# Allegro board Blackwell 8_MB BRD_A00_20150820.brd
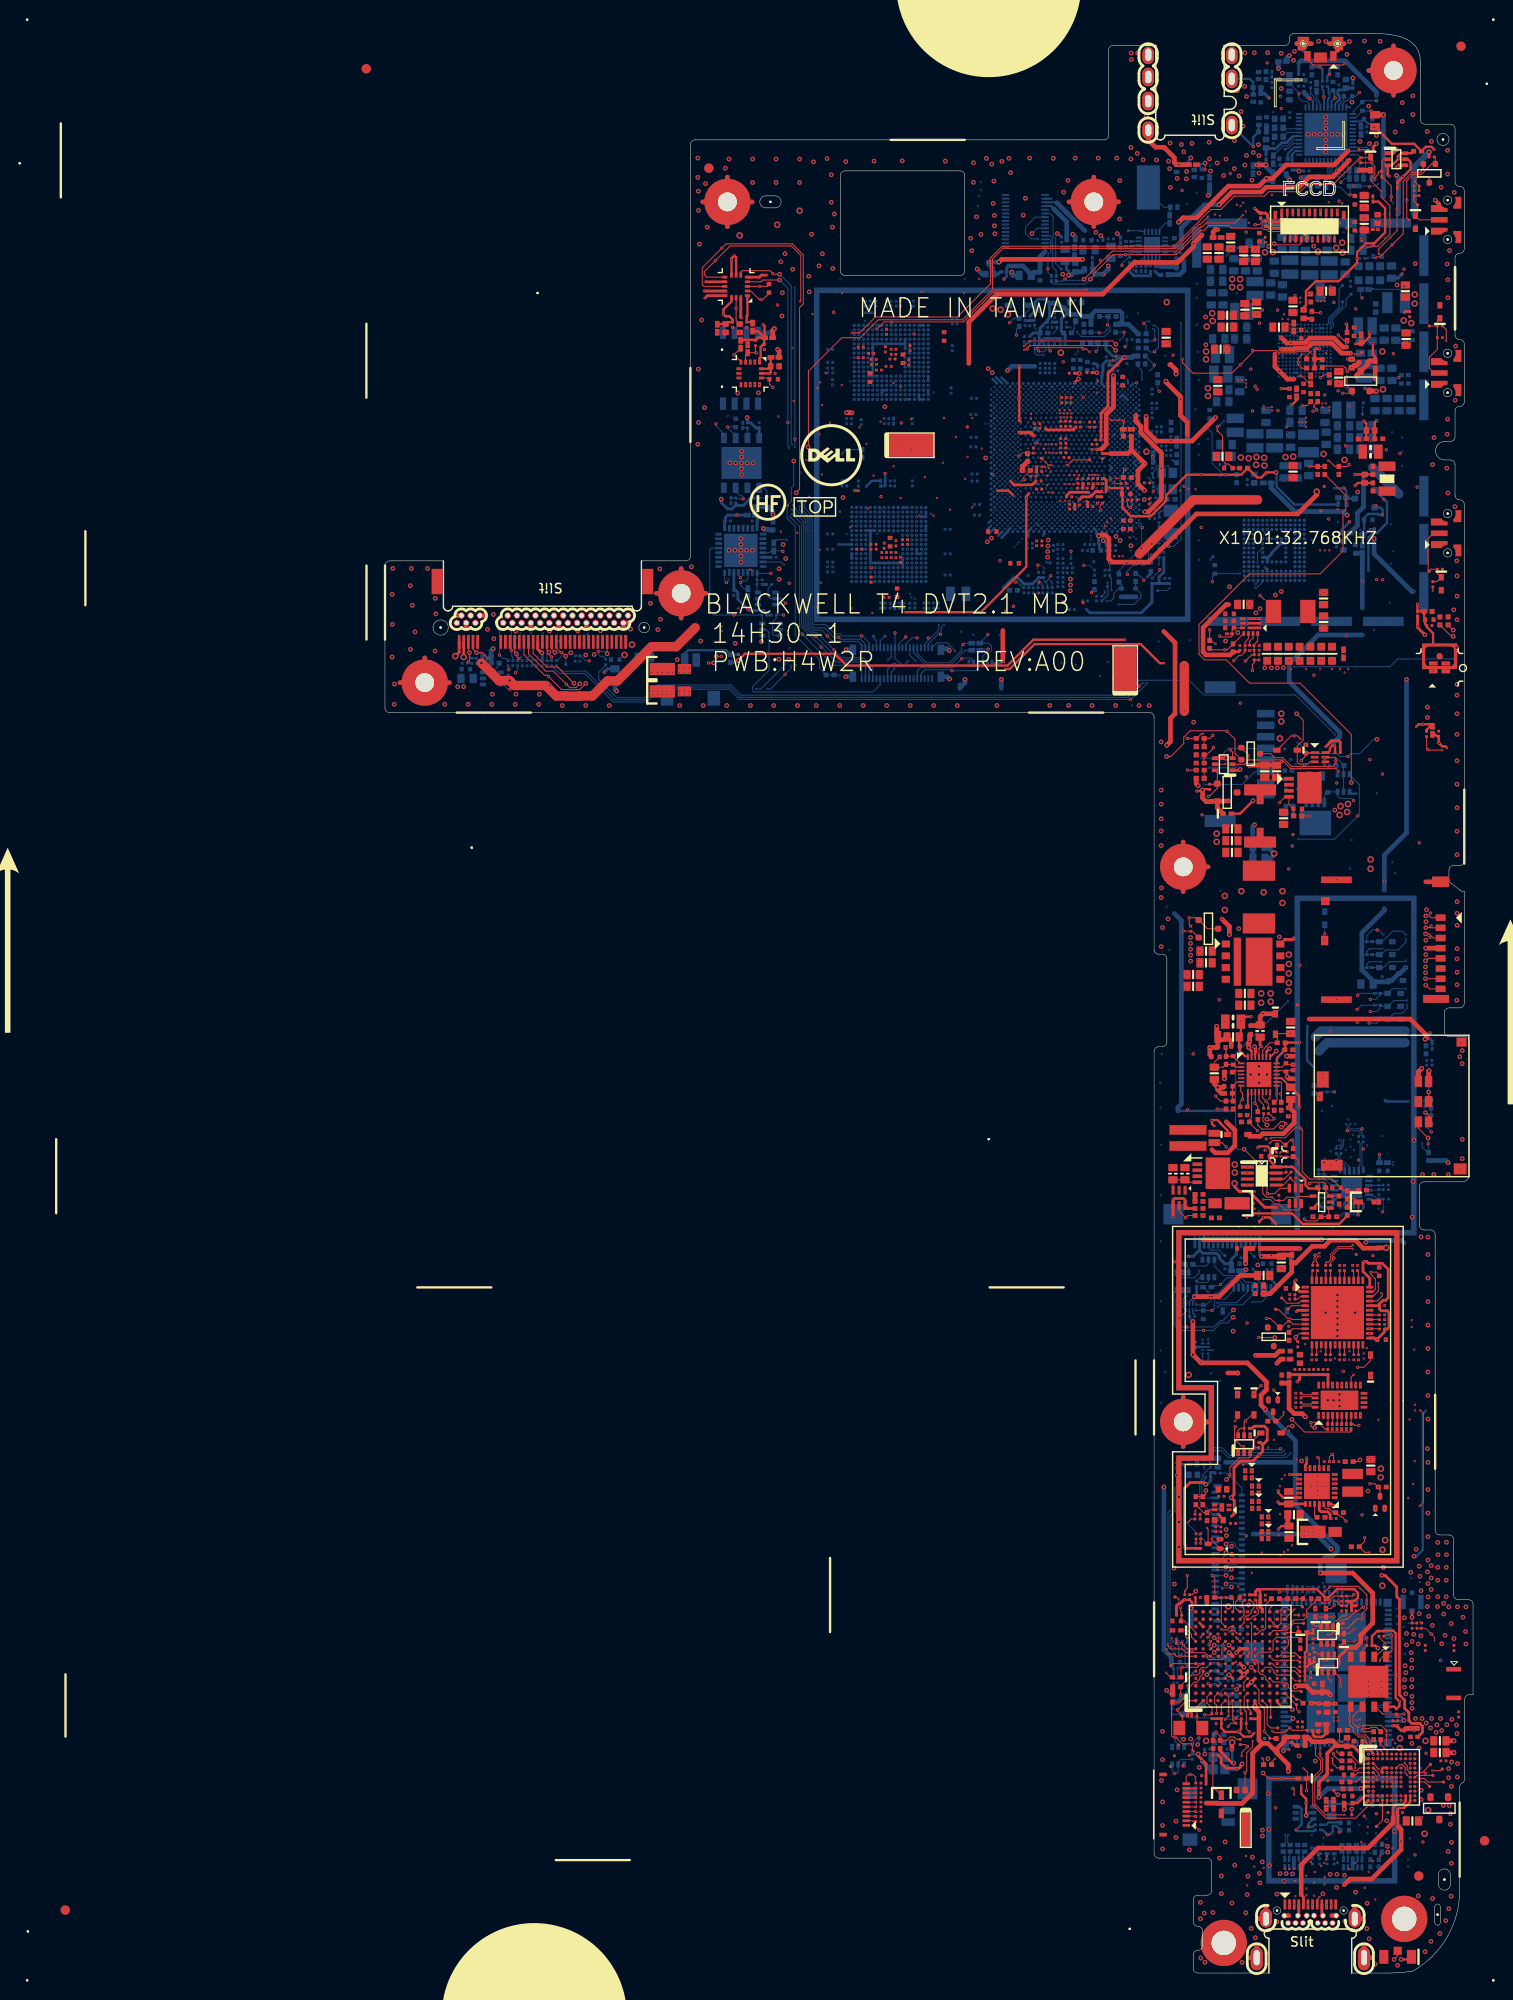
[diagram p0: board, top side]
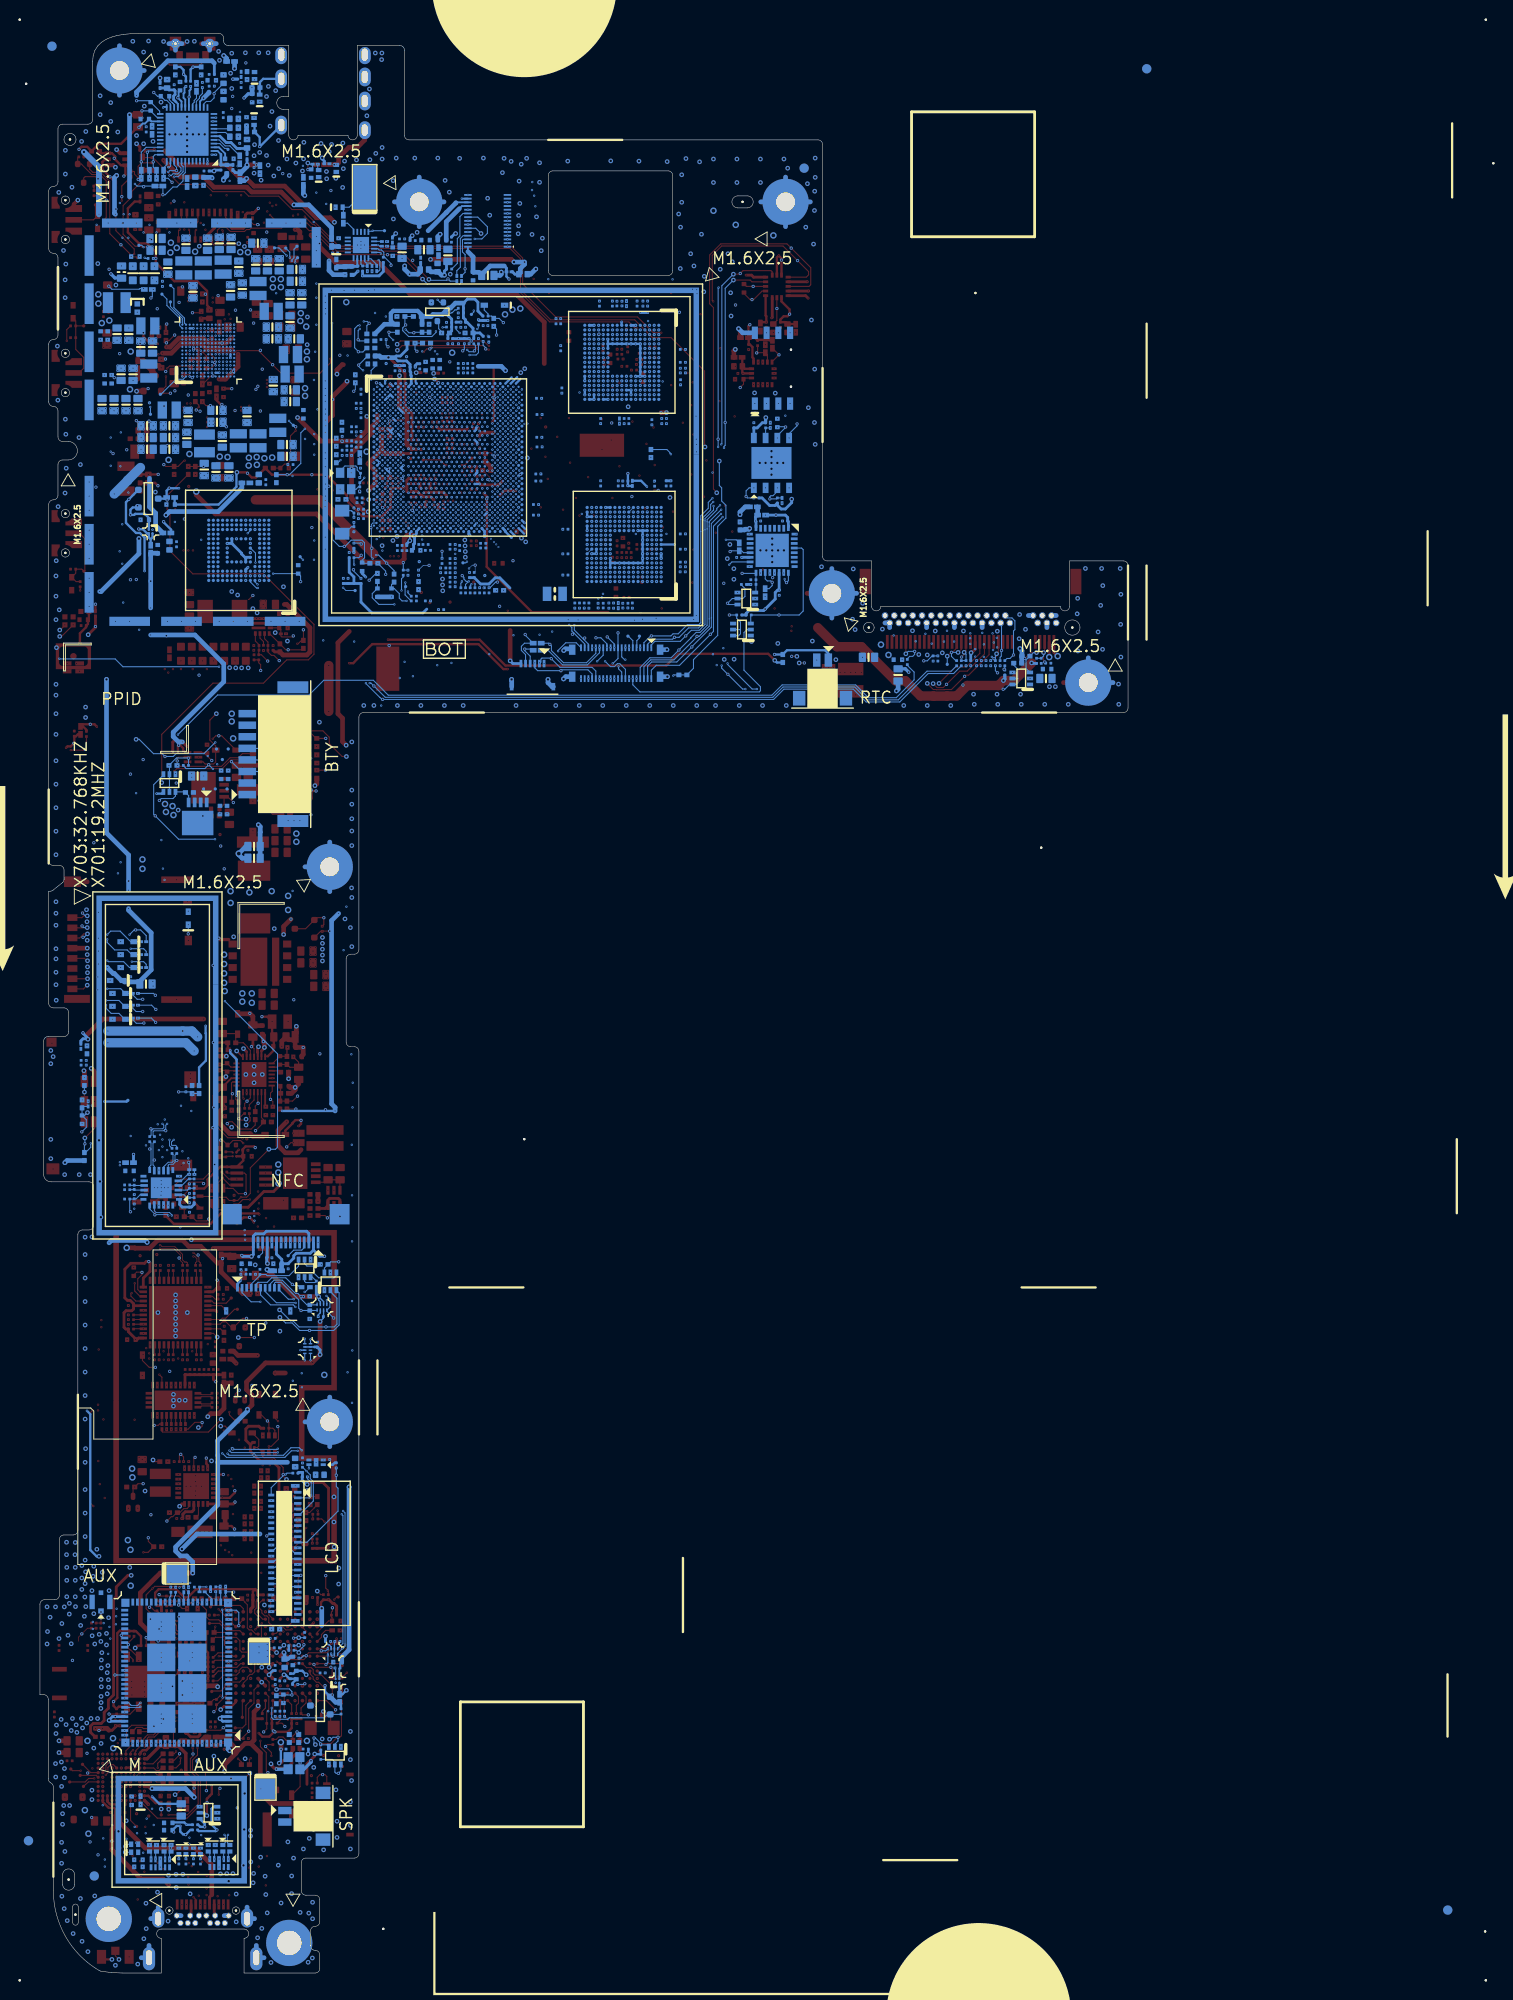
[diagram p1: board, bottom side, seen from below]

Outline 117.62 x 209.6 mm; copper layers: TOP, L2, L3SGND, L4SGND, L5, L6SGND, L7, BOTTOM. Coordinates in mm from the lower left corner of the outline.

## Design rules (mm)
constraint set DEFAULT: min track width 0.127, pair gap 0.102
net group 45R_EC_XTAL-MW: nets EC_XTAL1 EC_XTAL2
net group 45R_I2S-MW: nets CLK_I2S_MCLK CLK_I2S_MCLK_1
net group 45R_UART_BT-MW: nets UART_3_RXD_R UART_3_TXD_R
net group 45R_XTAL19D2M-MW: nets XTAL19_2_IN XTAL19_2_OUT
net group 45R_XTAL35D768K-MW: nets RTC_XTAL_IN RTC_XTAL_OUT
net group BIOS_HOLD#: nets BIOS_HOLD# FST_SPI_SOCK_D3
net group BIOS_WP#: nets BIOS_WP# FST_SPI_SOCK_D2
net group DDI0_TX0_DN: nets DDI0_TX0_DN DDI0_TX0_DN_ST
net group DDI0_TX0_DP: nets DDI0_TX0_DP DDI0_TX0_DP_ST
net group DDI0_TX1_DN: nets DDI0_TX1_DN DDI0_TX1_DN_ST
net group DDI0_TX1_DP: nets DDI0_TX1_DP DDI0_TX1_DP_ST
net group DDI0_TX2_DN: nets DDI0_TX2_DN DDI0_TX2_DN_ST
net group DDI0_TX2_DP: nets DDI0_TX2_DP DDI0_TX2_DP_ST
net group DDI0_TX3_DN: nets DDI0_TX3_DN DDI0_TX3_DN_ST
net group DDI0_TX3_DP: nets DDI0_TX3_DP DDI0_TX3_DP_ST
net group HP_MIC: nets HP_OUT_L HP_OUT_R
net group LPC_CLKOUT_0: nets LPC_CLKOUT_0 TPM_SCLK
net group MUX_ML0N: nets MUX_ML0N MUX_ML0N_ST
net group MUX_ML0P: nets MUX_ML0P MUX_ML0P_ST
net group MUX_ML1N: nets MUX_ML1N MUX_ML1N_ST
net group MUX_ML1P: nets MUX_ML1P MUX_ML1P_ST
net group MUX_ML2N: nets MUX_ML2N MUX_ML2N_ST
net group MUX_ML2P: nets MUX_ML2P MUX_ML2P_ST
net group MUX_ML3N: nets MUX_ML3N MUX_ML3N_ST
net group MUX_ML3P: nets MUX_ML3P MUX_ML3P_ST
net group SENSE: nets PMIC_VBATSENSE VSYS_SENSE_PMIC
net group USB3_0_RX+: nets USB3_0_RX+ USB3_0_RX+_L
net group USB3_0_RX-: nets USB3_0_RX- USB3_0_RX-_L
net group USB3_0_TX+: nets USB3_0_TX+ USB3_0_TX+_L
net group USB3_0_TX-: nets USB3_0_TX- USB3_0_TX-_L
net group USB3_A_INN: nets USB3_A_INN USB3_TXN0
net group USB3_A_INP: nets USB3_A_INP USB3_TXP0
net group USB3_B_OUTN: nets USB3_B_OUTN USB3_RXN0
net group USB3_B_OUTP: nets USB3_B_OUTP USB3_RXP0
net group 5V: nets +VUSB_5V_19V_R DCIN_OFF LCDBL_LED_A_R
net group 45R_CLK-MW: nets PLT_CLK1_CAM1 PLT_CLK1_CAM1_1 PLT_CLK1_CAM2 PLT_CLK1_CAM2_1
net group 45R_DDR_ZQ-MW: nets M0_ZQ0_A M0_ZQ0_B M0_ZQ1_A M0_ZQ1_B M1_ZQ0_A M1_ZQ0_B M1_ZQ1_A M1_ZQ1_B
net group 45R_DP_REDRIVER: nets DP_REDRIVER_ADDR_EQ DP_REDRIVER_CAD_SNK DP_REDRIVER_CAD_SRC DP_REDRIVER_EN_C DP_REDRIVER_RST DP_REDRIVER_SCL_CTL DP_REDRIVER_SCL_DDC DP_REDRIVER_SDA_CTL DP_REDRIVER_SDA_DDC DPR_HPD_IN DPR_HPD_OUT
net group 45R_EMMC-MW: nets EMMC_RESET#
net group 45R_EMMC_RCOMP-MW: nets EMMC_RCOMP
net group 45R_I2C-MW: nets CODEC_DMIC_1_DATA CODEC_DMIC_SCL DEBUG_I2C_1_SCL DEBUG_I2C_1_SDA DMIC_1_DATA DMIC_SCL GNSS0 GNSS1 GNSS_I2C_IRQ GYRO_CS I2C0_SCL I2C0_SDA I2C2_SCL I2C2_SDA I2C3_SCL I2C3_SDA I2C4_SCL I2C4_SDA I2C_0_SCL_EC I2C_0_SDA_EC I2C_1_SCL_CAM_R I2C_1_SCL_EC I2C_1_SDA_CAM_R I2C_1_SDA_EC I2C_4_SCL_EC I2C_4_SDA_EC I2C_5_SCL_3P3 I2C_5_SCL_EC I2C_5_SDA_3P3 I2C_5_SDA_EC I2C_7_SCL_EC I2C_7_SDA_EC I2CM_CLK I2CM_DATA ISH_I2C0_SCL ISH_I2C0_SDA ISH_I2C1_SCL ISH_I2C1_SCL_L ISH_I2C1_SDA ISH_I2C1_SDA_L PPMIC_DEBUG_I2C_CLK PPMIC_DEBUG_I2C_DATA PWR_CHG_CLK PWR_CHG_DATA RF_LTE_SIM1_CLK RF_LTE_SIM1_DATA SIM1_CLK_C SMB3_CLK_BATT SMB3_CLK_BATT_R SMB3_DAT_BATT SMB3_DAT_BATT_R TPS65982_I2C_ADDR TPS65982_I2C_IRQ1# TPS65982_I2C_SCL1 TPS65982_I2C_SCL2 TPS65982_I2C_SDA1 TPS65982_I2C_SDA2 TPS65982_SWD_CLK TPS65982_SWD_DATA
net group 45R_LPC-MW: nets LPC_AD0 LPC_AD1 LPC_AD2 LPC_AD3 LPC_CLKRUN# LPC_CLKRUN#_L LPC_FRAME# SOC_VBUSSNS
net group 45R_OTHER-MW: nets 2_4_LANE 2_4_LANE_DET 5V_COMP 5V_EN 5V_FB 5V_LBI 5V_LBO 5V_SVOUT AC_PRESENT AUDIO_CODEC_IRQ AUDIO_CODEC_IRQ_L AUDIO_CODEC_IRQ_R BPTHERM0 BRTC_EXTPAD BT_DEV_EN CAM_1_PWRDWN CAM_2_LSM CAM_2_PWRDWN COCO_ID CORE_PWROK DBG_RESETBTN# DCIN_DROP_DET# DDR3_DRAM_PWROK DDR3_VCCA_PWROK DEBUB_CS EC_BIST# GPIO133 GPIO223 GPIO224 GPIO_SUS3_C GYRO_INT1 HALL_INT# JACK_DET# LCD_BIST LCM_VDD_EN MIPI_BKLT_EN MIPI_PANEL_EN MODEM_SLPCLK NCF_SIMVCC NFC_SWP PANEL_EN PANEL_EN_L PANEL_EN_R PMIC_5V_EN PMIC_BATID PMIC_INT PMIC_LCM_BKLT_EN PMIC_LCM_BKLT_EN_R PMIC_PANEL_PWM0 PMIC_PANEL_PWM0_R PMIC_SYSTHERM0 PMIC_SYSTHERM1 PMIC_SYSTHERM2 PMIC_VBUS_IN PMIC_VDCIN PMU_BATTLOW# PROCHOT# RSMRST# SDIO_PWR_EN# SDMMC3_1P8_EN SLP_S0IX# SLP_S3# SLP_S4# SOC_PWRBTN# SOC_RTEST# SRT_CRST# SUS_PWRDOWNACK TOUCH_INT# TOUCH_RESET# TPM_GPIO0 TPM_GPIO0# USB_OTG_SOC_ID VBATL VOLUME_DOWN VOLUME_DOWN_SOC VOLUME_UP VOLUME_UP_SOC WL_DEV_EN WWAN_DETECT# WWAN_DETECT#_L
net group 45R_OTHERS-MW: nets 3V3_EC_EN 3V3_EC_VIN_ON# ACPI_INT# BATDRV# BATPRES# BL_FSET BL_ISET BOARD_ID CAMERA_1_RESET#_R CMP_7V+ CMP_7V- CODEC_CPN1 CODEC_CPN2 CODEC_CPP1 CODEC_CPP2 CODEC_CPVREF CODEC_DACREF CODEC_IN2P CODEC_VREF2 CPU_USB_OC# DBG_JTAG_CLK DBG_JTAG_RST# DBG_JTAG_TDI DBG_JTAG_TDO DBG_JTAG_TMS DBG_MSCLK DBG_MSDAT DBG_PIN1 DBG_UART_TX DCIN_OFF# DCIN_ON DDI0_HDP# DDI0_PLLOBS_N DDI0_PLLOBS_P DDI1_RCOMP_N DDI1_RCOMP_P DE303_INT1 DE303_INT2 DPR# EC5048_TX EC_AC_IN EC_AC_IN_R EC_BATT_PRES# EC_BATT_PRES#_R EC_FG_ALERT EC_GPIO002 EC_GPIO034 EC_GPIO036 EC_GPIO043 EC_GPIO047 EC_GPIO132 EC_GPIO201 EC_GPIO204 EC_GPIO212 EC_LAD0 EC_LAD1 EC_LAD2 EC_LAD3 EC_LCD_RST EC_LFRAME# EC_PROCHOT EC_PWRBTN# EC_RESETI# EC_SER_IRQ EC_SLP_S3# EC_SLP_S4# EC_SMI# EC_SMI#_R EC_SMI_REV# EC_SYS_PWR_EN EC_VCC_PWRGD EC_VCI_IN1# EC_VCI_IN2# EC_VCI_IN3# EC_VCI_IN4# EC_VCI_IN5# EC_VR_CAP EC_VREF_ADC ECOMPASS_C1 ECOMPASS_SETC ECOMPASS_SETP EN_19V_IN EN_19V_IN# EN_19V_IN_L EN_19V_IN_R EN_19V_IN_R# EN_DCIN_OP_VCC EN_V3P3_EC FG_ALERT_EC FSIN_REAR G601A31U_MRDLY GNSS_DISABLE# GNSS_DISABLE#_R GPIO151 GPIO152 GPIO166 GPIO222 GPIO_SUS2_C GPIO_SUS7 GYRO_CAP GYRO_INT2 GYRO_SA0 HOME_BTN_EC# HOME_BTN_SOC# HOME_KEY HOME_KEY_R HW_RST1 JACK_DET#_R LCD_BIST# LCM_HSYNC LCM_ID1 LCM_ID2 LCM_ID3 LCM_RST# LCM_XRES LCM_XRES1 LCM_XRES_R LRESET# MIC_CAP MODEM_PWR_ON MODEM_PWR_ON_R NFC_DWL_REQ NFC_EN_SEC NFC_HOST_INT_SEC OTG_ID P_RCOMP_N P_RCOMP_P PCIE_CLKREQ0# PEWAKE# PLTRST# PLTRST_EC PLTRST_N_3P3 PLTRST_N_3P3_R PMIC_PWRBTN# PMIC_PWRBTN_R# POWER_BUTTON_N PROJECT_ID1 PROJECT_ID2 PROX_CX PROX_CX_R PROX_DET# PWR_CHG_ACDET PWR_CHG_ACOK PWR_CHG_BATDRV# PWR_CHG_BTST PWR_CHG_BTST_A PWR_CHG_CELL PWR_CHG_CMPIN PWR_CHG_CMPIN_L PWR_CHG_CMSRC PWR_CHG_IADP PWR_CHG_PMON PWR_CHG_PROCHOT# PWR_CHG_REGN PWR_CHG_REGN_R PWR_SW_IN# R_OSC RF_LTE_SIM1_DET RF_LTE_SIM1_RST RF_W_DISABLE RF_W_DISABLE# RF_WWAN_DISABLE#_1P8 RTC_CLK SAR_A0 SAR_A1 SAR_INT SAR_INT_R SAR_RST SD3_CD# SIM_DETECT SLP_S0IX#_EC SLP_S0IX#_EC_R SLP_S3#_R SLP_S4#_R SOC_PROJECT_ID1 SOC_PROJECT_ID2 SPI_MODE SX_OFF SYS_PWR_ON SYS_PWR_ON# T0 T1 T2 T3 T4 T5 T6 T7 T8 T9 TOUCH_INT#_3P3 TOUCH_RESET#_3P3 TOUCH_RESET#_R TP_1P05_OBS TP_FUSE_PWRMON TP_ID1 TP_ID2 TP_VCCCORE2_OBS TP_VCCDDR_1P24_1P35_OBS TP_VCCSRAMGEN_1P15_OBS TP_VCCSRAMSOC_1P15_OBS TPS65982_DEBUG3 TPS65982_DEBUG3_R TPS65982_DEBUG4 TPS65982_DEBUG4_R TPS65982_GPIO0 TPS65982_GPIO0_R TPS65982_GPIO1 TPS65982_GPIO2 TPS65982_GPIO3 TPS65982_GPIO4_HPD TPS65982_GPIO6 TPS65982_GPIO7 TPS65982_GPIO8 TPS65982_I2C_IRQ2# TPS65982_I2C_IRQ2#_R TPS65982_LDO_BMC TPS65982_LSX_P2P TPS65982_LSX_P2R TPS65982_MRESET TPS65982_RESET# TPS65982_SS TPS65982_UART_RX TPS65982_UART_TX TPS65982_VOUT_3V3 TXE_WP TXE_WP# TYPE_C_IRQ# UART0_DBG_RXD UART0_DBG_TXD V3P3_SD_EN VCC0_SENSE VCC1_SENSE VCC_VSSSENSE VCCDSIPLL_1P24_1P35 VOLUME_DOWN_EC_IN VOLUME_DOWN_EC_OUT VOLUME_UP_EC_IN VOLUME_UP_EC_OUT VSET_EC WIFI_HOST_WAKE# WIFI_PERST# WWAN_WAKE# WWAN_WAKE_HOST#
net group 45R_REF_20MIL-MW: nets DDR3_M0_RCOMPPD DDR3_M1_RCOMPPD GPIO_RCOMP ICLK_ICOMP ICLK_RCOMP LPC_RCOMP MCSI_COMP MDSI_COMP SDIO3_RCOMP USB_HSIC_RCOMP USB_RCOMP USB_SSIC_RCOMP_N USB_SSIC_RCOMP_P
net group 45R_SDIO3_SD-MW: nets MC1CD# MC1CK_B MC1CM_B MC1CMD MC1DA0_B MC1DA1_B MC1DA2_B MC1DA3_B
net group 45R_SPI-MW: nets TPS65982_SPI_CLK TPS65982_SPI_HOLD TPS65982_SPI_MISO TPS65982_SPI_MOSI TPS65982_SPI_SSZ TPS65982_SPI_WP
net group 45R_USB3: nets USB3_DE1 USB3_DE2 USB3_EQ1 USB3_EQ2 USB3_OS1 USB3_OS2
net group 45R_WLA_CLK-MW: nets SUS_CLK_WLAN
net group 45R_XDP-MW: nets PMU_SLP_S0I3_N XDP_H_PRDY# XDP_H_PREQ# XDP_H_TCK XDP_H_TDI XDP_H_TDO XDP_H_TMS XDP_H_TRST#
net group 50R_RF_WIFI_ANT-MW: nets RF_WIFI_ANT_AUX_1
net group GND_200MIL: nets AUD_AGND_1 CAMF_AGND GND_L PMIC_AGND
net group POWER_10MIL: nets +V1P2SX +V1P8A_DE303_VDDIO +V1P8A_SENSOR +V3P3_EC_VBAT +V3P3_G601A31 +V3P3A_DE303_VDD +V3P3A_SENSOR +VDDR3_M0_OCAVREF +VDDR3_M1_OCAVREF +VDDR3_M1_OCAVREF_R +VDDR3_M1_ODQVREF +VDDR3_M1_ODQVREF_R +VREFB +VREFT +VRTC +VRTC_BAT +VRTC_BAT_R +VRTC_L +VRTC_R AMBER_LED AMBER_LED_EC AMBER_LED_R CAMERA_LED_R CAMERA_LED_R1 CAMERA_LED_R2 CC1 CC2 DCIN_OP_VCC DDR3_M0_OCAVREF DDR3_M0_ODQVREF DMIC1_VDD EMMC_VDDI HALL_VDD HP_OUT_L_1 HP_OUT_R_1 HPO_L_RC HPO_R_RC LCDBL_LED_C1 LCDBL_LED_C2 LCDBL_LED_C3 PWR_CHG_BAT PWR_CHG_IBAT PWR_CHG_ILIM PWR_CHG_VCC PWR_CHG_VCC_A TPS65982_LDO_1V8A TPS65982_LDO_1V8D TPS65982_LDO_3V3 VOUT_3V3 VPP VREF25 VREF_VTT WHITE_LED WHITE_LED_EC WHITE_LED_R
net group POWER_20MIL: nets 3V3_EC_VIN +V1P8_CODEC +V1P8A_WIFI +V2P8_CAM_VCM +V3P3_EC_L +V3P3_MUX +V3P3_TPM +V3P3_TPM_VSB +V3P3SX_SD +V3P3SX_SD_CONN BL_CIN CODEC_AVDD CODEC_CPVDD CODEC_CPVEE CODEC_CPVPP CODEC_DBVDD CODEC_DCVDD DOCK_DETECT# DVDD_REAR ISH_GPIO8 NFC_VCC_BOOST RF_LTE_UIM_PWR SAR_SVDD_V1P8 VDD_IO_NFC VDD_NFC_3P3 VDDD_DREG
net group POWER_80MIL: nets +V3P3_TPS65982 SPI3_CS0_N UART0_DATAIN

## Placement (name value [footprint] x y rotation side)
ANT1  IPEX-CON2-GP  [20449-001E]  111.02 40.1 180 bottom
ANT2  ANT-2P-29-GP  [AA077]  115.51 31.28 270 top
AUDIO1  AUDIO-JK496-GP  [2SJ3108-028111F]  87.02 207.3 180 top
BATT1  ACES-CON8-65-GP  [51483-00801-001]  90.28 131.72 90 bottom
BIOS1  W25Q128FWPIG-GP  [DFN8A5060-G435345H32]  38.54 163.19 0 bottom
BSKT1  SKT-SPI8P-5-GP-U  [SKT-SOIC8-2-UH121]  36.44 173.43 270 bottom
C501  SCD1U6D3V1KX-GP  [C0201H13]  77.84 151.33 180 bottom
C701  SC15P25V1JN-GP  [C0201H13]  82.97 162.35 180 bottom
C702  SC15P25V1JN-GP  [C0201H13]  83.04 160.32 0 bottom
C706  SCD1U10V1KX-GP  [C0201H13]  83.68 154.25 180 bottom
C707  SC18P25V1JN-GP  [C0201H13]  83.68 158.06 0 bottom
C708  SC18P25V1JN-GP  [C0201H13]  83.68 156.03 180 bottom
C709  SC1U6D3V1MX-GP  [C0201H14]  81.01 159.2 90 top
C710  SC10P50V2JN-4GP  [C402H22]  81.14 149.17 180 bottom
C711  SC10P50V2JN-4GP  [C402H22]  82.79 151.96 180 bottom
C712  SC10P50V2JN-4GP  [C402H22]  79.62 149.17 180 bottom
C1101  SCD47U4V1MX-GP  [C0201H13]  74.15 169.97 180 top
C1102  SCD47U4V1MX-GP  [C0201H13]  73.06 167.43 0 top
C1103  SCD47U4V1MX-GP  [C0201H13]  73.57 167.43 0 top
C1104  SCD47U4V1MX-GP  [C0201H13]  74.08 167.43 0 top
C1105  SC1U6D3V2KX-GP  [C402H22]  75.93 173.65 0 bottom
C1106  SC1U6D3V2KX-GP  [C402H22]  79.74 172.03 0 top
C1107  SCD47U4V1MX-GP  [C0201H13]  70.73 162.76 270 top
C1108  SCD47U4V1MX-GP  [C0201H13]  75.17 160.47 90 top
C1109  SCD47U4V1MX-GP  [C0201H13]  78.98 154 180 bottom
C1110  SCD47U4V1MX-GP  [C0201H13]  78.47 154 180 bottom
C1111  SC1U6D3V2KX-GP  [C402H22]  79.82 156.51 180 top
C1112  SC1U6D3V2KX-GP  [C402H22]  80.58 156.51 180 top
C1113  SCD47U4V1MX-GP  [C0201H13]  83.43 169.36 180 bottom
C1114  SCD47U4V1MX-GP  [C0201H13]  82.92 169.36 180 bottom
C1115  SCD47U4V1MX-GP  [C0201H13]  74.26 172.89 270 top
C1116  SCD47U4V1MX-GP  [C0201H13]  73.32 165.32 90 top
C1117  SCD47U4V1MX-GP  [C0201H13]  83.93 165.3 0 bottom
C1118  SCD47U4V1MX-GP  [C0201H13]  83.43 165.17 0 bottom
C1119  SCD47U4V1MX-GP  [C0201H13]  82.92 165.17 0 bottom
C1120  SCD47U4V1MX-GP  [C0201H13]  84.44 164.28 180 bottom
C1121  SCD47U4V1MX-GP  [C0201H13]  84.44 165.3 0 bottom
C1122  SCD47U4V1MX-GP  [C0201H13]  69.71 154 90 bottom
C1123  SCD47U4V1MX-GP  [C0201H13]  83.93 166.82 180 bottom
C1124  SCD47U4V1MX-GP  [C0201H13]  83.43 166.82 180 bottom
C1125  SCD47U4V1MX-GP  [C0201H13]  82.92 170.89 0 bottom
C1126  SCD47U4V1MX-GP  [C0201H13]  82.92 168.35 0 bottom
C1127  SCD47U4V1MX-GP  [C0201H13]  74.28 158.21 90 top
C1128  SCD47U4V1MX-GP  [C0201H13]  73.95 159.53 90 top
C1129  SCD47U4V1MX-GP  [C0201H13]  73.01 154.38 90 bottom
C1130  SCD47U4V1MX-GP  [C0201H13]  73.01 153.87 90 bottom
C1131  SCD47U4V1MX-GP  [C0201H13]  75.93 154.38 270 bottom
C1132  SCD47U4V1MX-GP  [C0201H13]  75.68 153.74 270 bottom
C1133  SCD47U4V1MX-GP  [C0201H13]  76.95 154.38 90 bottom
C1134  SCD47U4V1MX-GP  [C0201H13]  75.04 158.92 0 top
C1135  SCD47U4V1MX-GP  [C0201H13]  77.48 159.81 0 top
C1136  SCD47U4V1MX-GP  [C0201H13]  74.28 158.72 90 top
C1137  SCD47U4V1MX-GP  [C0201H13]  77.33 173.55 90 bottom
C1138  SCD47U4V1MX-GP  [C0201H13]  76.24 158.47 90 top
C1139  SCD47U4V1MX-GP  [C0201H13]  77.96 154 180 bottom
C1140  SCD47U4V1MX-GP  [C0201H13]  82.92 166.31 0 bottom
C1141  SCD47U4V1MX-GP  [C0201H13]  69.71 154.5 90 bottom
C1142  SCD47U4V1MX-GP  [C0201H13]  79.23 173.43 0 bottom
C1143  SCD47U4V1MX-GP  [C0201H13]  76.95 164.92 180 top
C1144  SCD47U4V1MX-GP  [C0201H13]  75.17 167.33 180 top
C1145  SCD47U4V1MX-GP  [C0201H13]  76.19 167.33 180 top
C1146  SCD47U4V1MX-GP  [C0201H13]  76.69 167.33 180 top
C1147  SCD47U4V1MX-GP  [C0201H13]  76.44 164.92 180 top
C1148  SCD47U4V1MX-GP  [C0201H13]  76.19 160.47 90 top
C1149  SCD47U4V1MX-GP  [C0201H13]  82.92 157.17 270 bottom
C1150  SCD47U4V1MX-GP  [C0201H13]  82.92 158.19 270 bottom
C1151  SCD47U4V1MX-GP  [C0201H13]  82.92 157.68 270 bottom
C1152  SCD47U4V1MX-GP  [C0201H13]  73.32 164.82 90 top
C1153  SCD47U4V1MX-GP  [C0201H13]  73.32 164.31 90 top
C1154  SC1U6D3V2KX-GP  [C402H22]  75.17 173.86 0 bottom
C1155  SC1U6D3V2KX-GP  [C402H22]  74.41 173.86 0 bottom
C1156  SCD47U4V1MX-GP  [C0201H13]  72.12 173.93 90 bottom
C1157  SCD47U4V1MX-GP  [C0201H13]  72.12 173.43 90 bottom
C1158  SCD47U4V1MX-GP  [C0201H13]  72.12 172.92 90 bottom
C1159  SCD47U4V1MX-GP  [C0201H13]  72.25 154 180 bottom
C1160  SCD47U4V1MX-GP  [C0201H13]  70.73 154.76 270 top
C1161  SCD47U4V1MX-GP  [C0201H13]  70.73 154.25 270 top
C1162  SCD47U4V1MX-GP  [C0201H13]  70.5 167.43 270 top
C1163  SCD47U4V1MX-GP  [C0201H13]  70.5 166.92 270 top
C1164  SCD47U4V1MX-GP  [C0201H13]  74.66 167.33 180 top
C1165  SCD47U4V1MX-GP  [C0201H13]  70.65 161.23 90 top
C1166  SCD47U4V1MX-GP  [C0201H13]  71.11 172.92 270 bottom
C1167  SCD47U4V1MX-GP  [C0201H13]  71.11 173.43 270 bottom
C1168  SCD47U4V1MX-GP  [C0201H13]  71.11 173.93 270 bottom
C1169  SCD47U4V1MX-GP  [C0201H13]  82.61 159.02 0 top
C1170  SCD47U4V1MX-GP  [C0201H13]  76.54 161.23 0 top
C1171  SCD47U4V1MX-GP  [C0201H13]  70.09 161.74 270 top
C1172  SCD47U4V1MX-GP  [C0201H13]  70.09 164.54 0 top
C1173  SCD47U4V1MX-GP  [C0201H13]  63.99 157.55 90 bottom
C1174  SCD47U4V1MX-GP  [C0201H13]  63.99 158.69 90 bottom
C1175  SCD47U4V1MX-GP  [C0201H13]  63.74 161.23 90 bottom
C1176  SCD47U4V1MX-GP  [C0201H13]  63.74 162 90 bottom
C1177  SCD47U4V1MX-GP  [C0201H13]  63.61 164.92 90 bottom
C1178  SCD47U4V1MX-GP  [C0201H13]  63.64 165.96 90 bottom
C1179  SCD47U4V1MX-GP  [C0201H13]  63.61 168.42 90 bottom
C1180  SCD47U4V1MX-GP  [C0201H13]  63.66 170.17 90 bottom
C1181  SCD47U4V1MX-GP  [C0201H13]  76.03 161.23 0 top
C1182  SCD47U4V1MX-GP  [C0201H13]  77.56 161.23 0 top
C1183  SCD47U4V1MX-GP  [C0201H13]  77.13 165.68 270 top
C1184  SCD47U4V1MX-GP  [C0201H13]  77.05 161.23 0 top
C1185  SCD47U4V1MX-GP  [C0201H13]  83.93 164.28 180 bottom
C1186  SCD47U4V1MX-GP  [C0201H13]  83.07 159.41 270 bottom
C1187  SCD47U4V1MX-GP  [C0201H13]  83.07 158.9 270 bottom
C1188  SC1U6D3V2KX-GP  [C402H22]  76.95 153.74 90 bottom
C1189  SC1U6D3V2KX-GP  [C402H22]  80.12 159.84 90 top
C1190  SCD1U10V1KX-GP  [C0201H13]  76.97 159.81 0 top
C1191  SCD1U10V1KX-GP  [C0201H13]  80 160.47 90 top
C1192  SCD47U4V1MX-GP  [C0201H13]  76.57 173.63 0 bottom
C1193  SCD47U4V1MX-GP  [C0201H13]  76.16 172.94 270 top
C1194  SCD47U4V1MX-GP  [C0201H13]  73.14 169.97 180 top
C1195  SCD47U4V1MX-GP  [C0201H13]  73.65 169.97 180 top
C1196  SCD47U4V1MX-GP  [C0201H13]  75.17 161.49 90 top
C1197  SCD47U4V1MX-GP  [C0201H13]  75.17 160.98 90 top
C1198  SCD47U4V1MX-GP  [C0201H13]  70.73 160.35 270 top
C1199  SCD47U4V1MX-GP  [C0201H13]  70.73 162.25 270 top
C1200  SCD47U4V1MX-GP  [C0201H13]  84.95 164.28 180 bottom
C1201  SCD47U4V1MX-GP  [C0201H13]  82.38 161.03 270 top
C1202  SCD47U4V1MX-GP  [C0201H13]  73.67 163.77 90 top
C1203  SCD47U4V1MX-GP  [C0201H13]  77.56 163.93 0 top
C1204  SCD47U4V1MX-GP  [C0201H13]  73.32 165.83 270 top
C1312  SC1U6D3V2KX-GP  [C402H22]  55.99 174.44 0 top
C1313  SCD47U4V1MX-GP  [C0201H13]  51.42 175.71 270 top
C1314  SCD1U6D3V1KX-GP  [C0201H13]  56.76 175.59 0 top
C1402  SC1U6D3V2KX-GP  [C402H22]  54.6 154.63 180 top
C1403  SCD1U6D3V1KX-GP  [C0201H13]  55.23 154.5 180 top
C1404  SCD47U4V1MX-GP  [C0201H13]  52.56 150.57 0 top
C1405  SC56P50V2JN-3-GP  [C402H22]  60.44 176.86 180 top
C1406  SC68P50V2JN-1-LL-GP  [C402H22]  52.44 172.41 0 top
C1407  SC47P50V2JN-3GP  [C402H22]  55.36 149.17 0 top
C1408  SC47P50V2JN-3GP  [C402H22]  65.65 155.77 270 top
C1409  SC47P50V2JN-3GP  [C402H22]  68.06 152.34 90 top
C1501  SCD47U4V1MX-GP  [C0201H13]  57.01 148.03 270 bottom
C1502  SCD47U4V1MX-GP  [C0201H13]  57.01 147.52 270 bottom
C1503  SCD47U4V1MX-GP  [C0201H13]  53.58 147.77 180 bottom
C1504  SCD47U4V1MX-GP  [C0201H13]  60.82 151.07 270 bottom
C1505  SCD47U4V1MX-GP  [C0201H13]  49.92 160.98 0 bottom
C1506  SCD47U4V1MX-GP  [C0201H13]  49.41 160.98 0 bottom
C1507  SCD47U4V1MX-GP  [C0201H13]  58.79 147.77 180 bottom
C1508  SCD47U4V1MX-GP  [C0201H13]  58.28 147.77 180 bottom
C1509  SCD47U4V1MX-GP  [C0201H13]  61.84 178.51 0 bottom
C1510  SCD47U4V1MX-GP  [C0201H13]  61.33 178.51 0 bottom
C1511  SCD47U4V1MX-GP  [C0201H13]  48.12 174.06 90 bottom
C1512  SCD47U4V1MX-GP  [C0201H13]  57.01 167.71 180 bottom
C1513  SCD47U4V1MX-GP  [C0201H13]  53.07 180.41 0 bottom
C1514  SCD47U4V1MX-GP  [C0201H13]  50.41 167.71 180 bottom
C1515  SCD47U4V1MX-GP  [C0201H13]  49.9 167.71 180 bottom
C1516  SCD47U4V1MX-GP  [C0201H13]  59.8 147.77 180 bottom
C1517  SCD47U4V1MX-GP  [C0201H13]  59.3 147.77 180 bottom
C1519  SCD47U4V1MX-GP  [C0201H13]  51.47 167.58 180 bottom
C1520  SCD47U4V1MX-GP  [C0201H13]  48.37 171.9 180 bottom
C1523  SCD47U4V1MX-GP  [C0201H13]  57.14 180.41 0 bottom
C1525  SCD47U4V1MX-GP  [C0201H13]  55.74 180.41 0 bottom
C1526  SCD47U4V1MX-GP  [C0201H13]  48.12 152.47 90 bottom
C1531  SCD47U4V1MX-GP  [C0201H13]  48.12 153.87 90 bottom
C1532  SCD47U4V1MX-GP  [C0201H13]  48.12 155.52 90 bottom
C1533  SCD47U4V1MX-GP  [C0201H13]  60.82 153.36 270 bottom
C1534  SCD47U4V1MX-GP  [C0201H13]  60.82 156.03 270 bottom
C1539  SCD47U4V1MX-GP  [C0201H13]  57.01 160.98 0 bottom
C1540  SCD47U4V1MX-GP  [C0201H13]  55.1 160.98 0 bottom
C1541  SCD47U4V1MX-GP  [C0201H13]  51.17 160.96 0 bottom
C1542  SCD47U4V1MX-GP  [C0201H13]  61.2 171.01 180 bottom
C1547  SCD47U4V1MX-GP  [C0201H13]  61.33 175.59 0 bottom
C1553  SCD47U4V1MX-GP  [C0201H13]  48.12 175.46 90 bottom
C1601  SCD1U10V1KX-GP  [C0201H13]  93.2 161.11 0 bottom
C1602  SC4D7U6D3V2MX-GP-U  [C402-TO0D2H26]  103.62 154.25 180 bottom
C1603  SCD1U10V1KX-GP  [C0201H13]  102.86 154.4 180 bottom
C1605  SC4D7U6D3V2MX-GP-U  [C402-TO0D2H26]  93.97 161.49 0 bottom
C1606  SC1U6D3V2KX-GP  [C402H22]  89.7 151.68 180 bottom
C1701  SC1U16V2KX-GP  [C402H22]  85.46 33.6 270 bottom
C1702  SCD1U10V1KX-GP  [C0201H13]  90.54 32.08 0 bottom
C1703  SC4700P50V2KX-1GP  [C402H22]  91.3 29.64 0 bottom
C1704  SCD1U10V1KX-GP  [C0201H13]  94.88 40.3 90 top
C1705  SC1U16V2KX-GP  [C402H22]  89.9 32.2 0 bottom
C1706  SC1U16V2KX-GP  [C402H22]  99.68 40.46 90 top
C1708  SCD1U10V1KX-GP  [C0201H13]  91.17 28.01 180 bottom
C1709  SCD1U10V1KX-GP  [C0201H13]  87.62 67.89 0 bottom
C1710  SC33P25V1JN-GP  [C0201H13]  86.47 27.76 90 top
C1711  SC33P25V1JN-GP  [C0201H13]  87.49 27.76 270 top
C1712  SC4D7U6D3V2MX-GP-U  [C402-TO0D2H26]  92.52 19.78 270 top
C1713  SC1U16V2KX-GP  [C402H22]  90.28 33.73 0 bottom
C1714  SCD1U10V1KX-GP  [C0201H13]  92.19 31.44 180 bottom
C1715  SC2200P50V2KX-2GP  [C402H22]  91.93 40.58 270 top
C1716  SC100P25V1KX-GP  [C0201H13]  87.11 112.85 0 top
C1717  SCD1U10V1KX-GP  [C0201H13]  90.66 40.58 90 top
C1718  SCD1U10V1KX-GP  [C0201H13]  92.47 36.16 270 bottom
C1719  SC10U6D3V2MX-GP-U  [C402-TO0D2H28]  91.17 33.47 0 bottom
C1720  SCD1U10V1KX-GP  [C0201H13]  95.36 25.34 270 top
C1721  SCD1U10V1KX-GP  [C0201H13]  86.47 35.83 90 bottom
C1722  SC1U16V2KX-GP  [C402H22]  85.58 38.04 270 top
C1723  SCD1U10V1KX-GP  [C0201H13]  85.46 35.83 90 bottom
C1726  SCD1U10V1KX-GP  [C0201H13]  90.13 26.97 270 top
C1727  SCD1U10V1KX-GP  [C0201H13]  92.19 28.01 180 bottom
C1728  SCD1U10V1KX-GP  [C0201H13]  92.19 32.96 180 bottom
C1729  SCD1U10V1KX-GP  [C0201H13]  87.06 32.43 90 bottom
C1730  SCD1U10V1KX-GP  [C0201H13]  94.88 40.84 90 top
C1731  SCD1U10V1KX-GP  [C0201H13]  91.43 31.57 90 bottom
C1732  SCD1U10V1KX-GP  [C0201H13]  91.68 28.01 180 bottom
C1802  SC10P50V2JN-4GP  [C402H22]  37.91 167.51 180 bottom
C1803  SCD1U6D3V1KX-GP  [C0201H13]  40.45 167.25 0 bottom
C2001  SC2D2U6D3V2KX-GP  [C402H22]  106.29 200.35 90 bottom
C2002  SC2D2U6D3V2KX-GP  [C402H22]  102.48 203.91 180 bottom
C2003  SC4D7U6D3V2MX-GP-U  [C402-TO0D2H26]  96.63 198.45 270 bottom
C2004  SCD1U10V1KX-GP  [C0201H13]  101.84 204.16 0 bottom
C2005  SCD1U10V1KX-GP  [C0201H13]  101.33 204.16 0 bottom
C2006  SC4D7U6D3V2MX-GP-U  [C402-TO0D2H26]  97.78 204.67 0 bottom
C2007  SC4D7U6D3V2MX-GP-U  [C402-TO0D2H26]  96.63 199.41 90 bottom
C2008  SC2D2U6D3V2KX-GP  [C402H22]  104.1 202.81 270 bottom
C2009  SC2D2U6D3V2KX-GP  [C402H22]  105.65 201.72 180 bottom
C2010  SC4D7U6D3V2MX-GP-U  [C402-TO0D2H26]  96.63 200.38 270 bottom
C2011  SC4D7U6D3V2MX-GP-U  [C402-TO0D2H26]  97.78 202.89 180 bottom
C2012  SCD1U10V1KX-GP  [C0201H13]  96.02 197.45 0 bottom
C2013  SC10U6D3V2MX-GP-U  [C402-TO0D2H28]  95.24 197.68 0 bottom
C2014  SC2D2U6D3V2KX-GP  [C402H22]  97.42 194.94 180 bottom
C2015  SCD1U10V1KX-GP  [C0201H13]  98.06 195.12 180 bottom
C2016  SCD1U10V1KX-GP  [C0201H13]  103.11 203.78 0 bottom
C2017  SC4D7U6D3V2MX-GP-U  [C402-TO0D2H26]  103.87 204.16 0 bottom
C2018  SC2D2U6D3V2KX-GP  [C402H22]  99.05 204.54 90 bottom
C2019  SCD1U10V1KX-GP  [C0201H13]  99.05 203.91 90 bottom
C2020  SC2D2U6D3V2KX-GP  [C402H22]  97.14 196.06 90 bottom
C2021  SCD1U16V1KX-GP  [C0201H13]  99.6 194.74 90 bottom
C2022  SC10U6D3V2MX-GP-U  [C402-TO0D2H28]  100.82 193.62 180 bottom
C2101  SCD1U10V1KX-GP  [C0201H13]  112.89 145.61 90 top
C2102  SC1U6D3V2KX-GP  [C402H22]  112.89 146.25 90 top
C2103  SC680P25V1KX-GP  [C0201H13]  91.3 24.2 270 bottom
C2104  SC680P25V1KX-GP  [C0201H13]  88.89 24.2 90 bottom
C2201  SC22P50V2GN-GP  [C402H22]  88.3 194.46 180 bottom
C2202  SC22P50V2GN-GP  [C402H22]  95.29 200.1 0 bottom
C2203  SC22P50V2GN-GP  [C402H22]  94.68 202.61 180 bottom
C2204  SCD01U6D3V1KX-1-GP  [C0201H13]  106.13 199.23 0 bottom
C2205  SCD01U6D3V1KX-1-GP  [C0201H13]  94.47 195.4 0 bottom
C2301  SC4D7U6D3V3KX-GP  [C603H36]  106.16 106.88 90 bottom
C2302  SCD1U10V1KX-GP  [C0201H13]  107.81 107.39 0 bottom
C2401  SCD1U10V1KX-GP  [C0201H13]  101.84 95.5 180 bottom
C2402  SC1U6D3V1MX-GP  [C0201H14]  112.89 98.62 90 bottom
C2403  SCD1U10V1KX-GP  [C0201H13]  112.89 98.12 90 bottom
C2404  SC33P50V2JN-3GP  [C402H22]  113.07 92.22 180 bottom
C2501  SCD1U10V2KX-5GP  [C402H22]  75.93 187.27 90 bottom
C2502  SC10U6D3V3MX-GP  [C603H38]  76.11 186.23 90 bottom
C2503  SC10U6D3V3MX-GP  [C603H38]  73.52 185.62 180 bottom
C2504  SCD1U10V2KX-5GP  [C402H22]  74.15 187.27 270 bottom
C2505  SC22P25V1JN-GP  [C0201H13]  77.33 187.22 270 bottom
C2506  SC22P25V1JN-GP  [C0201H13]  73.14 187.32 0 bottom
C2507  SC4D7U6D3V2MX-GP-U  [C402-TO0D2H26]  65.39 183.59 90 bottom
C2508  SCD1U10V2KX-5GP  [C402H22]  70.8 183.38 180 bottom
C2509  SC10U6D3V3MX-GP  [C603H38]  69.2 183.46 90 bottom
C2510  SC10U6D3V3MX-GP  [C603H38]  105.85 189.02 180 top
C2511  SCD1U10V2KX-5GP  [C402H22]  94.52 187.57 0 top
C2512  SC10U6D3V3MX-GP  [C603H38]  91.43 187.02 0 top
C2513  SC22P25V1JN-GP  [C0201H13]  95.16 187.29 0 top
C2514  SCD1U10V2KX-5GP  [C402H22]  104.84 188.77 180 top
C2515  SC4D7U6D3V2MX-GP-U  [C402-TO0D2H26]  74.64 184.3 180 bottom
C2516  SC4D7U6D3V2MX-GP-U  [C402-TO0D2H26]  76.06 184.09 90 bottom
C2517  SC4D7U6D3V2MX-GP-U  [C402-TO0D2H26]  107.3 189.56 180 top
C2518  SC10U6D3V3MX-GP  [C603H38]  78.47 185.95 180 bottom
C2519  SC10U6D3V3MX-GP  [C603H38]  105.85 191.43 0 top
C2520  SCD1U10V2KX-5GP  [C402H22]  79.49 186.02 180 bottom
C2521  SCD1U10V2KX-5GP  [C402H22]  104.84 191.59 0 top
C2902  SCD22U6D3V2KX-1GP  [C402H22]  107.71 18.61 0 bottom
C2903  SC22U6D3V3MX-1-GP  [C603H40]  114.03 23.82 90 top
C2904  SC22U6D3V3MX-1-GP  [C603H40]  114.03 25.09 90 top
C2905  SCD1U16V1KX-GP  [C0201H13]  114.41 22.93 90 top
C2906  SC1U50V3KX-GP  [C603H32]  111.06 16.43 270 top
C2907  SCD01U50V2KX-1GP  [C402H22]  106.97 12.24 90 bottom
C2908  SCD01U50V2KX-1GP  [C402H22]  106.97 11.48 90 bottom
C2909  SCD01U50V2KX-1GP  [C402H22]  110.86 25.98 180 top
C2910  SCD01U50V2KX-1GP  [C402H22]  111.62 25.98 180 top
C2911  SC220P25V1KX-2-GP  [C0201H13]  108.7 17.34 270 top
C2912  SC220P25V1KX-2-GP  [C0201H13]  109.71 17.34 90 top
C2913  SC4D7U6D3V2MX-GP-U  [C402-TO0D2H26]  104 24.96 180 top
C2914  SC1U10V2KX-1GP  [C402H22]  104.13 19.12 270 top
C2915  SC10U6D3V3MX-GP  [C603H38]  102.35 17.62 180 bottom
C2916  SC1U10V2KX-1GP  [C402H22]  105.22 25.06 270 top
C2917  SC1U10V2KX-1GP  [C402H22]  104.13 18.36 270 top
C2918  SC1U10V2KX-1GP  [C402H22]  104.13 21.41 270 top
C3001  SCD1U10V1KX-GP  [C0201H13]  105.12 76.19 0 top
C3002  SCD1U10V1KX-GP  [C0201H13]  104.61 76.19 0 top
C3003  SCD1U10V1KX-GP  [C0201H13]  103.72 76.19 0 top
C3004  SCD1U10V1KX-GP  [C0201H13]  103.21 76.19 0 top
C3005  SCD1U10V1KX-GP  [C0201H13]  102.2 76.19 0 top
C3006  SCD1U10V1KX-GP  [C0201H13]  101.69 76.19 0 top
C3007  SCD1U10V1KX-GP  [C0201H13]  100.8 76.19 0 top
C3008  SCD1U10V1KX-GP  [C0201H13]  100.29 76.19 0 top
C3009  SCD1U10V1KX-GP  [C0201H13]  107.78 71.11 90 top
C3010  SCD1U10V1KX-GP  [C0201H13]  107.78 70.61 90 top
C3011  SCD1U10V1KX-GP  [C0201H13]  105.24 66.54 180 top
C3012  SCD1U10V1KX-GP  [C0201H13]  104.74 66.54 180 top
C3013  SCD1U10V1KX-GP  [C0201H13]  103.72 66.54 180 top
C3014  SCD1U10V1KX-GP  [C0201H13]  103.21 66.54 180 top
C3015  SCD1U10V1KX-GP  [C0201H13]  102.2 66.54 180 top
C3016  SCD1U10V1KX-GP  [C0201H13]  101.69 66.54 180 top
C3017  SCD1U10V1KX-GP  [C0201H13]  100.7 66.54 180 top
C3018  SCD1U10V1KX-GP  [C0201H13]  100.19 66.54 180 top
C3024  SC1U10V2KX-1GP  [C402H22]  97.85 73.99 270 top
C3025  SC2D2U10V2KX-GP  [C402H22]  107.48 75.79 180 top
C3031  SCD1U10V1KX-GP  [C0201H13]  107.78 72.13 90 top
C3032  SC10U6D3V2MX-GP-U  [C402-TO0D2H28]  98.92 66.37 0 top
C3033  SCD01U50V2KX-1GP  [C402H22]  107.73 68.45 90 top
C3102  SCD01U6D3V1KX-1-GP  [C0201H13]  98.36 64.94 180 top
C3103  SCD01U6D3V1KX-1-GP  [C0201H13]  98.87 64.94 180 top
C3104  SCD01U6D3V1KX-1-GP  [C0201H13]  99.38 64.94 180 top
C3105  SCD01U6D3V1KX-1-GP  [C0201H13]  99.88 64.94 180 top
C3106  SCD01U6D3V1KX-1-GP  [C0201H13]  100.39 64.94 180 top
C3107  SCD01U6D3V1KX-1-GP  [C0201H13]  100.9 64.94 180 top
C3108  SCD01U6D3V1KX-1-GP  [C0201H13]  101.41 64.94 180 top
C3127  SCD01U6D3V1KX-1-GP  [C0201H13]  101.92 64.94 180 top
C3132  SCD1U16V1KX-GP  [C0201H13]  101.46 82.49 180 bottom
C3133  SCD01U50V2KX-1GP  [C402H22]  107.94 86.69 270 bottom
C3138  SCD1U10V1KX-GP  [C0201H13]  103.34 88.84 0 bottom
C3139  SCD1U10V1KX-GP  [C0201H13]  102.83 88.84 0 bottom
C3140  SCD1U10V1KX-GP  [C0201H13]  98.74 62.15 270 top
C3141  SCD1U10V1KX-GP  [C0201H13]  98.74 62.66 270 top
C3142  SCD1U10V1KX-GP  [C0201H13]  98.74 61.64 270 top
C3143  SCD1U10V1KX-GP  [C0201H13]  98.74 61.13 270 top
C3144  SCD1U10V1KX-GP  [C0201H13]  15.35 141.55 0 bottom
C3145  SCD1U10V1KX-GP  [C0201H13]  15.86 141.55 0 bottom
C3146  SCD1U10V1KX-GP  [C0201H13]  16.37 141.55 0 bottom
C3147  SCD1U10V1KX-GP  [C0201H13]  14.85 141.55 0 bottom
C3148  SCD1U10V1KX-GP  [C0201H13]  105.75 90.11 0 bottom
C3149  SCD1U10V1KX-GP  [C0201H13]  105.24 90.11 0 bottom
C3401  SC10U6D3V2MX-GP-U  [C402-TO0D2H28]  90.54 52.27 90 top
C3402  SCD01U6D3V1KX-GP  [C0201H13]  90.41 51.51 90 top
C3403  SC10U6D3V2MX-GP-U  [C402-TO0D2H28]  90.16 48.94 270 top
C3404  SCD01U6D3V1KX-GP  [C0201H13]  90.08 47.7 270 top
C3405  SCD1U16V1KX-GP  [C0201H13]  90.08 48.2 270 top
C3406  SCD1U16V1KX-GP  [C0201H13]  91.68 48.59 90 top
C3407  SC10U6D3V2MX-GP-U  [C402-TO0D2H28]  87.36 53.84 270 bottom
C3408  SC10U6D3V2MX-GP-U  [C402-TO0D2H28]  90.03 55.16 180 bottom
C3409  SCD01U6D3V1KX-GP  [C0201H13]  89.24 55.39 180 bottom
C3410  SCD01U6D3V1KX-GP  [C0201H13]  86.3 55.21 0 bottom
C3901  SC10U10V3MX-GP  [C603H36]  96.89 76.78 0 top
C3902  SC1U10V2KX-1GP  [C402H22]  91.93 76.65 270 bottom
C3903  SCD1U6D3V1KX-GP  [C0201H13]  90.79 76.37 180 bottom
C3904  SC1U10V2KX-1GP  [C402H22]  92.57 78.3 270 top
C3905  SCD1U6D3V1KX-GP  [C0201H13]  92.82 77.29 90 bottom
C4001  SCD1U6D3V1KX-GP  [C0201H13]  17 141.55 180 bottom
C4002  SC10U10V3MX-GP  [C603H36]  8.88 139.9 270 bottom
C4006  SC10U10V3MX-GP  [C603H36]  24.85 140.28 180 bottom
C4007  SCD1U6D3V1KX-GP  [C0201H13]  8.62 141.55 270 bottom
C4008  SC2D2U25V3KX-GP  [C603H38]  28.05 142.18 270 bottom
C4009  SC22P50V2GN-GP  [C402H22]  24.88 141.93 90 bottom
C4010  SC22P50V2GN-GP  [C402H22]  8.75 140.91 270 bottom
C4101  SC1U10V2KX-1GP  [C402H22]  85.33 187.02 0 bottom
C4102  SC100P25V1KX-GP  [C0201H13]  85.71 185.87 270 bottom
C4103  SC1U10V2KX-1GP  [C402H22]  83.88 183.97 180 bottom
C4104  SC100P25V1KX-GP  [C0201H13]  83.25 184.2 180 bottom
C4201  SC10U6D3V2MX-GP-U  [C402-TO0D2H28]  36.82 177.74 0 top
C4202  SCD1U10V1KX-GP  [C0201H13]  37.58 178.13 0 top
C4203  SCD1U10V1KX-GP  [C0201H13]  39.1 178.13 0 top
C4206  SCD1U10V1KX-GP  [C0201H13]  41.01 175.71 0 top
C4207  SC10U6D3V2MX-GP-U  [C402-TO0D2H28]  42.15 173.63 90 top
C4208  SCD1U10V1KX-GP  [C0201H13]  41.9 172.87 90 top
C4209  SCD01U50V2KX-1GP  [C402H22]  42.02 172.23 90 top
C4210  SCD1U10V1KX-GP  [C0201H13]  113.91 133.93 180 top
C4301  SC10U6D3V3MX-GP  [C603H38]  94.98 75.38 90 top
C4302  SCD1U6D3V1KX-GP  [C0201H13]  95.62 76.02 270 bottom
C4303  SC2D2U6D3V2MX-GP  [C402H22]  95.36 76.65 270 bottom
C4304  SCD1U6D3V1KX-GP  [C0201H13]  94.6 75.51 90 bottom
C4305  SC1KP25V2JX-GP  [C402H22]  88.45 72.66 0 bottom
C4306  SC1KP25V2JX-GP  [C402H22]  88.45 71.14 180 bottom
C4308  SCD1U6D3V1KX-GP  [C0201H13]  87.26 70.94 270 bottom
C4309  SCD1U6D3V1KX-GP  [C0201H13]  95.62 75.51 270 bottom
C4401  SC10U10V3MX-GP  [C603H36]  106.56 54.83 180 top
C4402  SC10U10V3MX-GP  [C603H36]  97.7 51.35 180 top
C4403  SC10U25V3MX-GP  [C603H40]  98.26 49.52 270 top
C4404  SCD1U16V1KX-GP  [C0201H13]  102.55 49.12 90 top
C4405  SCD1U16V1KX-GP  [C0201H13]  101.81 55.27 270 top
C4406  SC10U25V3MX-GP  [C603H40]  97.73 47.65 0 top
C5215  SC22U6D3V3MX-1-GP  [C603H40]  101.46 145.99 0 top
C5216  SC22U10V3MX-1-GP  [C603H42]  102.37 142.57 0 top
C5217  SC22U10V3MX-1-GP  [C603H42]  101.21 142.57 0 top
C5218  SC22U6D3V3MX-1-GP  [C603H40]  92.82 147.9 90 top
C5219  SC2200P50V2KX-2GP  [C402H22]  91.3 146.88 270 top
C5220  SC22U10V3MX-1-GP  [C603H42]  100.04 142.57 0 top
C5221  SC22U10V3MX-1-GP  [C603H42]  98.87 142.57 0 top
C5222  SC22U10V3MX-1-GP  [C603H42]  97.7 142.57 0 top
C5223  SC1U10V2KX-1GP  [C402H22]  91.3 146.12 270 top
C5224  SC1U10V2KX-1GP  [C402H22]  91.3 145.36 270 top
C5225  SC22U10V3MX-1-GP  [C603H42]  96.53 142.57 0 top
C5226  SC22U10V3MX-1-GP  [C603H42]  95.36 142.57 0 top
C5227  SC22U6D3V3MX-1-GP  [C603H40]  101.46 148.53 180 top
C5228  SC220P25V1KX-2-GP  [C0201H13]  94.47 142.18 180 top
C5401  SCD22U6D3V2KX-1GP  [C402H22]  99.55 132.28 180 top
C5402  SC33P25V1JN-GP  [C0201H13]  114.03 176.73 270 top
C5403  SC33P25V1JN-GP  [C0201H13]  114.03 151.71 270 top
C5404  SC33P25V1JN-GP  [C0201H13]  106.54 196.97 270 top
C5405  SC33P25V1JN-GP  [C0201H13]  111.26 192.35 0 top
C5406  SCD1U10V1KX-GP  [C0201H13]  111.52 193.11 270 top
C5703  SCD1U10V1KX-GP  [C0201H13]  37.07 156.92 270 bottom
C5704  SCD1U10V1KX-GP  [C0201H13]  37.71 149.17 180 bottom
C5705  SCD1U10V1KX-GP  [C0201H13]  42.02 152.98 270 bottom
C5706  SCD1U10V1KX-GP  [C0201H13]  39.99 156.92 90 bottom
C5707  SCD1U10V1KX-GP  [C0201H13]  40.5 150.57 270 bottom
C5709  SCD22U10V2KX-1GP  [C402H22]  41.52 182.06 180 top
C5710  SC4D7U6D3V2MX-GP-U  [C402-TO0D2H26]  38.34 177.74 0 top
C5711  SC1U16V2KX-GP  [C402H22]  96.89 89.48 270 top
C5712  SC1U16V2KX-GP  [C402H22]  95.19 88.26 270 top
C5713  SC1KP25V2JX-GP  [C402H22]  103.75 16.23 270 bottom
C5714  SC1KP25V2JX-GP  [C402H22]  103.75 15.44 270 bottom
CABLE1  SPRING-159-GP  [SPR260243H68]  103.62 43.18 0 bottom
CABLE2  SPRING-159-GP  [SPR260243H68]  93.94 35.4 90 bottom
CABLE3  SPRING-159-GP  [SPR260243H68]  93.24 20.7 90 bottom
CAMF1  PSC-CONN21D-1-GP  [FH35C-21S-0D3SHW-50]  99.94 189.96 180 top
CAMR1  HRS-CONN30E-2-GP  [DF30FC-30DS]  69.22 189.35 270 bottom
CLED1  LED-W-38-GP  [LED1608AKH20]  107.02 200.16 0 top
CN1  SUL-1315A1M-GP  [SUL-1315A1M]  87.75 186.49 270 bottom
CN2  SUL-1315A1M-GP  [SUL-1315A1M]  91.02 189.11 0 bottom
CN3  SUL-1315A1M-GP  [SUL-1315A1M]  96.92 189.11 180 bottom
CN4  SUL-1315A1M-GP  [SUL-1315A1M]  102.82 189.11 0 bottom
CN5  SUL-1315A1M-GP  [SUL-1315A1M]  108.72 189.11 0 bottom
CN6  SUL-1315A1M-GP  [SUL-1315A1M]  112.3 185.6 270 bottom
CN7  SUL-1315A1M-GP  [SUL-1315A1M]  112.3 180.4 90 bottom
CN8  SUL-1315A1M-GP  [SUL-1315A1M]  112.3 175.2 270 bottom
CN9  SUL-1315A1M-GP  [SUL-1315A1M]  112.3 170 90 bottom
CN10  SUL-1315A1M-GP  [SUL-1315A1M]  112.3 159.6 270 bottom
CN11  SUL-1315A1M-GP  [SUL-1315A1M]  112.3 154.4 90 bottom
CN12  SUL-1315A1M-GP  [SUL-1315A1M]  112.3 149.2 270 bottom
CN13  SUL-1315A1M-GP  [SUL-1315A1M]  107.92 146.07 0 bottom
CN14  SUL-1315A1M-GP  [SUL-1315A1M]  102.32 146.07 0 bottom
CN15  SUL-1315A1M-GP  [SUL-1315A1M]  96.72 146.07 0 bottom
CN16  SUL-1315A1M-GP  [SUL-1315A1M]  91.12 146.07 0 bottom
CPU1  CHERRY-TRAIL-GP-U  [BGA1380M17-UH41]  73.52 163.77 0 bottom
D1701  DB2U31600L-GP  [SOD923-10D6AKH16]  85.58 31.95 90 top
D1702  DB2U31600L-GP  [SOD923-10D6AKH16]  85.58 37.03 90 top
D1703  DB2U31600L-GP  [SOD923-10D6AKH16]  100.57 38.93 0 top
D1704  DB2U31600L-GP  [SOD923-10D6AKH16]  101.71 38.93 0 top
D1705  DB2U31600L-GP  [SOD923-10D6AKH16]  88.89 74.11 270 bottom
D1706  DB2U31600L-GP  [SOD923-10D6AKH16]  91.05 125.29 270 top
D1707  DB2U31600L-GP  [SOD923-10D6AKH16]  103.67 36.24 0 top
D1708  DB2U31600L-GP  [SOD923-10D6AKH16]  85.58 184.73 0 bottom
D1709  UDZV-5D6B-GP  [SOD323-2513AKH36]  90.41 18.23 180 top
D1710  DB2U31600L-GP  [SOD923-10D6AKH16]  98.94 35.53 180 top
D2101  VARISTOR-5V-1-GP  [VARISTOR-402-H19]  90.66 25.34 180 bottom
D2102  VARISTOR-5V-1-GP  [VARISTOR-402-H19]  89.65 25.34 180 bottom
D2103  VARISTOR-5V-1-GP  [VARISTOR-402-H19]  112.76 147.14 270 top
D2106  VARISTOR-5V-1-GP  [VARISTOR-402-H19]  114.03 146.12 0 top
D2107  VARISTOR-5V-1-GP  [VARISTOR-402-H19]  114.92 146.12 0 top
D2201  AZ5725-01FDR7G-GP  [SOD882-10D6-1H20]  94.42 205.05 0 bottom
D2202  AZ5725-01FDR7G-GP  [SOD882-10D6-1H20]  94.47 200.1 180 bottom
D2203  AZ5725-01FDR7G-GP  [SOD882-10D6-1H20]  93.86 202.61 0 bottom
D2204  AZ5725-01FDR7G-GP  [SOD882-10D6-1H20]  87.49 194.46 0 bottom
D2205  AZ5725-01FDR7G-GP  [SOD882-10D6-1H20]  85.58 195.02 0 bottom
D2301  AZ5125-01H-R7G-GP  [SOD-523-4H28]  109.08 104.47 270 bottom
D2302  AZ5125-01H-R7G-GP  [SOD-523-4H28]  109.08 103.07 270 bottom
D2303  AZ5125-01H-R7G-GP  [SOD-523-4H28]  108.19 111.45 270 bottom
D2304  AZ5125-01H-R7G-GP  [SOD-523-4H28]  108.19 110.05 270 bottom
D2305  AZ5125-01H-R7G-GP  [SOD-523-4H28]  109.33 107.26 270 bottom
D2306  AZ5125-01H-R7G-GP  [SOD-523-4H28]  108.19 108.66 270 bottom
D2307  AZ5125-01H-R7G-GP  [SOD-523-4H28]  109.08 105.86 270 bottom
D2308  AZ5125-01H-R7G-GP  [SOD-523-4H28]  101.59 113.99 0 bottom
D2401  EGA10402V12A0-GP  [D402H18]  112.53 99.77 180 bottom
D2402  EGA10402V12A0-GP  [D402H18]  101.18 95.47 180 bottom
D2403  EGA10402V12A0-GP  [D402H18]  112.81 96.34 180 bottom
D2404  EGA10402V12A0-GP  [D402H18]  113.07 93.92 180 bottom
D2405  EGA10402V12A0-GP  [D402H18]  112.81 88.23 0 bottom
D2901  DB2U31600L-GP  [SOD923-10D6AKH16]  106.74 18.66 180 bottom
D2902  DB2U31600L-GP  [SOD923-10D6AKH16]  99.17 21.03 90 top
D3001  SD103AWS-2-GP  [SOD323AKH38]  106.54 65.68 0 top
D3401  BAT54CTB-GP  [SC75-1D6-312H24]  89.62 46.38 90 top
D3403  SD103AWS-2-GP  [SOD323AKH38]  92.16 61.41 180 top
D3404  SD103AWS-2-GP  [SOD323AKH38]  93.94 61.41 180 top
D3405  SD103AWS-2-GP  [SOD323AKH38]  95.77 58.36 270 top
D4001  SMD34JGP-GP-U  [SOD123AK-3719-UH40]  30.85 140.91 270 top
D4002  SMD34JGP-GP-U  [SOD123AK-3719-UH40]  30.85 138.5 270 top
D4101  PESD5V0U1BL-GP-U1  [SOD882-10D6-1H20]  85.28 190.83 90 bottom
D4401  SMD34JGP-GP-U  [SOD123AK-3719-UH40]  101.18 47.67 270 top
D4402  BAT54CTB-GP  [SC75-1D6-312H24]  107.56 50.87 0 top
D4403  BAT54CTB-GP  [SC75-1D6-312H24]  96 61.29 180 top
D4501  VARISTOR-5V-1-GP  [VARISTOR-402-H19]  88.12 131.64 270 top
D4502  VARISTOR-5V-1-GP  [VARISTOR-402-H19]  88.12 129.1 270 top
D4503  VARISTOR-5V-1-GP  [VARISTOR-402-H19]  88.12 132.53 270 top
D5401  AZ5125-01H-R7G-GP  [SOD-523-4H28]  114.03 179.52 180 top
D5402  AZ5125-01H-R7G-GP  [SOD-523-4H28]  114.18 150.13 0 top
D5403  AZ5125-01H-R7G-GP  [SOD-523-4H28]  111.39 189.2 0 top
D5404  AZ5125-01H-R7G-GP  [SOD-523-4H28]  106.54 195.52 0 top
D5405  BAT54CW-1-GP  [SOT-323H44]  112.89 194.48 180 top
D5411  BAT54CW-1-GP  [SOT-323H44]  93.59 131.77 270 top
D5412  SD103AWS-2-GP  [SOD323AKH38]  68.49 180.23 90 bottom
D5413  AZ5B25-01F-GP  [D0201H13]  100.27 12.06 180 bottom
D5414  AZ5B25-01F-GP  [D0201H13]  101.03 12.06 180 bottom
D5415  AZ5B25-01F-GP  [D0201H13]  102.6 12.06 180 bottom
D5416  AZ5B25-01F-GP  [D0201H13]  101.84 12.06 180 bottom
D5417  AZ5725-01FDR7G-GP  [SOD882-10D6-1H20]  107.38 13.05 90 bottom
D5418  AZ5725-01FDR7G-GP  [SOD882-10D6-1H20]  107.38 13.91 90 bottom
DB2  HRS-CON6-11-GP-U  [FH34SRJ-6S-0D5SH-50-U]  64.38 139.01 180 bottom
ECDBG1  ACES-CON10-55-GP  [50521-01001-001]  84.11 18.21 270 top
ECOMP3  LSM303DTR-GP  [LGA16-3030-H40]  37.96 182.27 270 top
EMMC1  KLMCG8GEND-B031-GP  [BGA153G115130-1H40]  96.13 153.74 0 bottom
GYRO1  L3GD20HTR-GP  [LGA16-3030-H40]  39.48 172.87 0 top
H1  HOLE197R79-GP  [HOLE197R79]  109.02 205.6 0 bottom
H3  HOLE197R103-GP  [HOLE197R103]  110.18 5.85 0 bottom
H4  HOLE197R103-GP  [HOLE197R103]  90.67 3.25 0 bottom
H5  HOLE197R79-GP  [HOLE197R79]  86.29 59.56 0 bottom
H6  HOLE197R79-GP  [HOLE197R79]  86.29 119.54 0 bottom
H7  HOLE197R79-GP  [HOLE197R79]  32.02 149.1 0 bottom
H8  HOLE197R79-GP  [HOLE197R79]  4.3 139.45 0 bottom
H9  HOLE197R79-GP  [HOLE197R79]  76.62 191.4 0 bottom
H10  HOLE197R79-GP  [HOLE197R79]  37.02 191.4 0 bottom
HALL1  S-5712ACDL1-M3T1U-GP  [SOT23-2D8-123H52]  113.97 17.8 180 top
HKEY1  SW-TACT-3P-5-GP-U  [SKRTLAE010-U]  114.87 189.46 90 top
JUSBC1  SKT-USB30-GP-U1  [SKT-USB30-118098-U1]  100.03 1.65 0 top
L3101  DLP0NSC280HL2L-GP  [LD65D85-4PH20]  97.47 13.48 90 bottom
L3102  DLP0NSC280HL2L-GP  [LD65D85-4PH20]  99.05 13.48 90 bottom
L3103  DLP0NSN900HL2L-GP-U1  [LD85D65-4P-1H20]  100.65 13.2 180 bottom
L3104  DLP0NSN900HL2L-GP-U1  [LD85D65-4P-1H20]  102.22 13.2 180 bottom
L3105  DLP0NSC280HL2L-GP  [LD65D85-4PH20]  105.4 13.48 90 bottom
L3106  DLP0NSC280HL2L-GP  [LD65D85-4PH20]  103.82 13.48 90 bottom
L3401  FILTER-4P-132-GP  [LD65D85-4PH20]  93.36 53.89 0 top
L3402  FILTER-4P-132-GP  [LD65D85-4PH20]  94.09 52.24 0 top
L3403  FILTER-4P-132-GP  [LD65D85-4PH20]  94.09 50.59 0 top
L3404  FILTER-4P-132-GP  [LD65D85-4PH20]  95.13 48.92 0 top
L3405  FILTER-4P-132-GP  [LD65D85-4PH20]  95.13 47.32 0 top
L4401  IND-10UH-271-GP  [L2520-D620H48]  104.61 52.98 0 top
L5202  COIL-1UH-74-GP  [L4442-D820H48]  97.9 147.14 270 top
LCD1  HRS-CONN45D-GP-U  [FH35C-45S-0D3SHW-50-U]  90.02 45.35 90 bottom
LED1  LED-YW-4-GP  [LED3020-3P-6H44]  109.47 1.75 180 top
MIC1  MICROPHONE-108-GP  [WM7211IMS-RV]  114 141.1 180 top
MSD1  SDCARD-8P-10-GP  [503398-0891]  114.1 110.84 270 top
MSIM1  SKT-SIMM6-26-GP  [SF56S006V4AR2000]  101.37 93.7 90 top
NFC1  ACES-CON15-17-GP  [51548-01541-W01]  91.05 82 0 bottom
NGFF1  SKT-MINI67P-24-GP-U  [AS0BC56-R15BB-7H-U]  17.02 145.4 180 top
NOREF  -  [unnamed]  16.5 181.55 0 top
NOREF#2  *  [unnamed]  35.01 195.04 0 top
NOREF#3  -  [unnamed]  119.11 204.16 0 top
NOREF#4  *  [unnamed]  118.86 14.3 0 top
NOREF#5  -  [#2]  -40.78 118.82 270 top
NOREF#6  -  [#2]  46.47 158.44 0 top
NOREF#7  -  [unnamed]  113.78 6.31 0 top
NOREF#8  -  [#2]  -89.93 33.98 0 top
NOREF#9  *  [unnamed]  -34.56 6.8 0 top
NOREF#10  -  [#2]  65.26 214.88 180 top
NOREF#11  -  [unnamed]  114.52 10.1 0 top
NOREF#12  -  [unnamed]  114.37 198.15 0 top
NOREF#13  -  [unnamed]  119.81 211.09 0 top
NOREF#14  *  [unnamed]  116.32 208.22 0 top
NOREF#15  -  [#2]  6.02 214.9 0 top
NOREF#16  -  [unnamed]  -39.49 195.57 0 top
NOREF#17  -  [#2]  41.39 158.95 0 top
NOREF#18  -  [unnamed]  80.5 4.77 0 top
NOREF#19  -  [#2]  -15 -15.55 0 top
NOREF#20  *  [unnamed]  -2.02 205.79 0 top
NOREF#21  -  [#2]  48.25 164.03 0 top
NOREF#22  -  [unnamed]  119.81 -0.79 0 top
NOREF#23  -  [unnamed]  9.38 121.61 0 top
NOREF#24  -  [unnamed]  -38.68 211.09 0 top
NOREF#25  -  [#2]  121.65 111.07 270 top
NOREF#26  -  [unnamed]  -38.6 4.49 0 top
NOREF#27  *  [unnamed]  111.75 10.49 0 top
NOREF#28  -  [#2]  16.14 -4.6 0 top
NOREF#29  -  [unnamed]  -38.68 -0.79 0 top
NOREF#30  -  [#2]  -15 -15.55 0 top
NOREF#31  -  [unnamed]  65.26 90.11 0 top
NOREF#32  -  [unnamed]  41.67 191.4 90 top
NOREF#33  -  [#2]  -15 -15.55 0 top
NOREF#34  *  [unnamed]  35.01 195.04 180 bottom
NOREF#35  -  [#2]  -40.78 118.82 90 bottom
NOREF#36  *  [unnamed]  -34.56 6.8 180 bottom
NOREF#37  -  [#2]  73.9 143.07 180 bottom
NOREF#38  *  [unnamed]  118.86 14.3 180 bottom
NOREF#39  -  [#2]  16.75 194.38 180 bottom
NOREF#40  *  [unnamed]  111.75 10.49 180 bottom
NOREF#41  *  [unnamed]  116.32 208.22 180 bottom
NOREF#42  -  [#2]  121.65 111.07 90 bottom
NOREF#43  *  [unnamed]  -2.02 205.79 180 bottom
NOREF#44  -  [#2]  65.52 22.55 180 bottom
NOREF#45  -  [#2]  47.61 2.1 180 bottom
PC4501  SCD1U25V2KX-GP  [C402H22]  97.27 129.48 0 bottom
PC4502  SCD1U25V2KX-GP  [C402H22]  98.03 129.48 0 bottom
PC4503  SC10U10V3MX-GP  [C603H36]  100.57 129.36 270 bottom
PC4504  SCD1U25V2KX-GP  [C402H22]  97.4 125.67 180 bottom
PC4505  SC33P50V2JN-5-GP  [C402H22]  98.16 125.67 180 bottom
PC4601  SCD1U25V2KX-GP  [C402H22]  98.16 98.62 180 top
PC4602  SCD01U50V2KX-1GP  [C402H22]  91.17 95.83 90 top
PC4603  SC10U10V3MX-GP  [C603H36]  91.55 123.64 270 top
PC4604  SC10U25V3MX-GP  [C603H40]  92.95 105.86 90 top
PC4605  SC10U10V3MX-GP  [C603H36]  97.14 124.79 180 top
PC4606  SC10U10V3MX-GP  [C603H36]  91.55 121.1 270 top
PC4607  SC1U50V3KX-GP  [C603H32]  91.68 101.16 270 top
PC4608  SC10U25V3MX-GP  [C603H40]  92.95 104.59 90 top
PC4609  SCD1U25V2KX-GP  [C402H22]  98.16 97.1 0 top
PC4610  SC10U10V3MX-GP  [C603H36]  95.11 129.87 180 top
PC4611  SC10U10V3MX-GP  [C603H36]  96.38 129.87 180 top
PC4612  SCD1U25V2KX-GP  [C402H22]  90.41 100.02 90 top
PC4613  SCD1U25V2KX-GP  [C402H22]  89.78 99 90 top
PC4614  SC10U25V3MX-GP  [C603H40]  88.76 110.43 270 top
PC4615  SCD047U25V2KX-GP  [C402H22]  93.59 101.93 0 top
PC4616  SC2D2U10V3KX-1GP  [C603H36]  97.9 102.18 180 top
PC4617  SCD01U50V2KX-1GP  [C402H22]  98.67 125.8 270 top
PC4618  SC10U25V3MX-GP  [C603H40]  88.76 109.16 270 top
PC4619  SC10U25V3MX-GP  [C603H40]  87.36 107.89 270 top
PC4620  SCD1U25V2KX-GP  [C402H22]  91.68 98.62 0 top
PC4621  SCD1U25V2KX-GP  [C402H22]  97.4 97.86 0 top
PC4622  SC10U10V3MX-GP  [C603H36]  91.55 122.37 270 top
PC4623  SC1U50V3KX-GP  [C603H32]  89.65 97.23 0 top
PC4624  SCD1U25V2KX-GP  [C402H22]  91.93 100.15 270 top
PC4625  SC10U25V3MX-GP  [C603H40]  87.36 106.62 270 top
PC4626  SC100P50V2JN-3GP  [C402H22]  92.44 93.16 0 top
PC4627  SC100P50V2JN-3GP  [C402H22]  93.2 93.16 0 top
PC4628  SC1U10V2KX-1GP  [C402H22]  97.65 93.04 0 top
PC4629  SC10U10V3MX-GP  [C603H36]  94.47 120.47 90 bottom
PC4630  SC10U10V3MX-GP  [C603H36]  94.47 121.74 90 bottom
PC4631  SCD1U25V2KX-GP  [C402H22]  102.86 84.86 270 top
PC4701  SC22U6D3V3MX-1-GP  [C603H40]  90.59 178.43 180 bottom
PC4702  SC22U6D3V3MX-1-GP  [C603H40]  89.32 180.92 0 bottom
PC4703  SC22U6D3V3MX-1-GP  [C603H40]  90.59 180.92 0 bottom
PC4704  SC22U6D3V3MX-1-GP  [C603H40]  94.3 184.6 0 bottom
PC4705  SC22U6D3V3MX-1-GP  [C603H40]  91.76 184.6 0 bottom
PC4706  SC22U6D3V3MX-1-GP  [C603H40]  93.03 184.6 0 bottom
PC4707  SC22U6D3V3MX-1-GP  [C603H40]  91.05 179.14 90 top
PC4708  SC22U6D3V3MX-1-GP  [C603H40]  90.13 176.6 270 bottom
PC4709  SC22U6D3V3MX-1-GP  [C603H40]  101.74 165.86 0 bottom
PC4710  SC22U6D3V3MX-1-GP  [C603H40]  97.19 162.22 180 bottom
PC4711  SC22U6D3V3MX-1-GP  [C603H40]  97.9 165.55 0 bottom
PC4712  SC22U6D3V3MX-1-GP  [C603H40]  98.59 162.22 180 bottom
PC4713  SC22U6D3V3MX-1-GP  [C603H40]  90.92 165.17 90 bottom
PC4714  SC4D7U6D3V3MX-2GP  [C603H36]  98.49 167.58 90 bottom
PC4715  SC22U6D3V3MX-1-GP  [C603H40]  90.56 171.09 270 bottom
PC4716  SC22U6D3V3MX-1-GP  [C603H40]  90.56 169.82 270 bottom
PC4717  SC10U10V3MX-GP  [C603H36]  95.24 168.22 180 bottom
PC4718  SC10U10V3MX-GP  [C603H36]  92.49 177.87 90 bottom
PC4719  SC10U10V3MX-GP  [C603H36]  92.49 176.6 90 bottom
PC4720  SC10U10V3MX-GP  [C603H36]  98.49 168.88 90 bottom
PC4721  SC4D7U6D3V3MX-2GP  [C603H36]  95.74 181.99 0 bottom
PC4722  SC10U10V3MX-GP  [C603H36]  97.01 181.78 0 bottom
PC4723  SC22U6D3V3MX-1-GP  [C603H40]  91.05 177.87 90 top
PC4724  SC22U6D3V3MX-1-GP  [C603H40]  89.9 182.82 90 bottom
PC4725  SC22U6D3V3MX-1-GP  [C603H40]  89.9 184.09 90 bottom
PC4726  SC22U6D3V3MX-1-GP  [C603H40]  90.54 163.9 270 top
PC4727  SC22U6D3V3MX-1-GP  [C603H40]  98.16 162.25 0 top
PC4728  SC22U6D3V3MX-1-GP  [C603H40]  99.86 162.48 180 bottom
PC4729  SC22U6D3V3MX-1-GP  [C603H40]  90.92 163.9 90 bottom
PC4730  SC22U6D3V3MX-1-GP  [C603H40]  90.03 171.52 180 top
PC4732  SC22U6D3V3MX-1-GP  [C603H40]  90.33 175.48 90 top
PC4801  SC22U6D3V3MX-1-GP  [C603H40]  96.96 186.91 0 bottom
PC4802  SC22U6D3V3MX-1-GP  [C603H40]  96.13 184.35 180 bottom
PC4803  SC22U6D3V3MX-1-GP  [C603H40]  98.23 186.91 0 bottom
PC4804  SC22U6D3V3MX-1-GP  [C603H40]  109.28 177.11 180 bottom
PC4805  SC22U6D3V3MX-1-GP  [C603H40]  92.82 185.62 180 top
PC4806  SC22U6D3V3MX-1-GP  [C603H40]  99.5 186.82 0 bottom
PC4807  SC22U6D3V3MX-1-GP  [C603H40]  101.84 186.82 0 bottom
PC4808  SC22U6D3V3MX-1-GP  [C603H40]  94.22 179.9 0 top
PC4809  SC22U6D3V3MX-1-GP  [C603H40]  103.8 184.25 180 bottom
PC4810  SC22U6D3V3MX-1-GP  [C603H40]  94.09 185.62 180 top
PC4811  SC10U10V3MX-GP  [C603H36]  92.39 171.55 180 bottom
PC4812  SC10U10V3MX-GP  [C603H36]  105.45 175.71 0 bottom
PC4813  SC22U10V3MX-1-GP  [C603H42]  105.24 183.69 0 bottom
PC4814  SC4D7U6D3V3MX-2GP  [C603H36]  106.72 175.71 0 bottom
PC4815  SC22U10V3MX-1-GP  [C603H42]  106.41 183.69 0 bottom
PC4816  SC4D7U6D3V3MX-2GP  [C603H36]  101.61 168.22 180 bottom
PC4817  SC22U10V3MX-1-GP  [C603H42]  107.58 183.69 0 bottom
PC4818  SC22U6D3V3MX-1-GP  [C603H40]  108.01 177.11 180 bottom
PC4819  SC22U6D3V3MX-1-GP  [C603H40]  92.95 179.75 0 top
PC4820  SC22U6D3V3MX-1-GP  [C603H40]  101.08 181.68 0 bottom
PC4821  SC22U6D3V3MX-1-GP  [C603H40]  84.44 176.73 0 top
PC4822  SC22U6D3V3MX-1-GP  [C603H40]  103.62 167.2 90 bottom
PC4823  SC22U6D3V3MX-1-GP  [C603H40]  103.62 165.93 90 bottom
PC4824  SC22U6D3V3MX-1-GP  [C603H40]  106.03 167.2 270 bottom
PC4825  SC22U6D3V3MX-1-GP  [C603H40]  106.03 164.66 270 bottom
PC4826  SC22U6D3V3MX-1-GP  [C603H40]  106.03 165.93 270 bottom
PC4827  SC22U6D3V3MX-1-GP  [C603H40]  103.62 164.66 90 bottom
PC4828  SC22U6D3V3MX-1-GP  [C603H40]  110.91 169.49 180 bottom
PC4829  SC22U6D3V3MX-1-GP  [C603H40]  108.32 169.49 180 bottom
PC4830  SC22U6D3V3MX-1-GP  [C603H40]  109.61 169.49 180 bottom
PC4831  SC10U10V3MX-GP  [C603H36]  110.3 181.76 180 top
PC4832  SC22U6D3V3MX-1-GP  [C603H40]  107.02 169.49 180 bottom
PC4833  SC22U6D3V3MX-1-GP  [C603H40]  107.56 172.77 0 bottom
PC4834  SC22U6D3V3MX-1-GP  [C603H40]  108.85 172.77 0 bottom
PC4836  SC22U6D3V3MX-1-GP  [C603H40]  94.07 186.94 90 bottom
PC4837  SC22U6D3V3MX-1-GP  [C603H40]  110.37 176.58 0 top
PC4839  SC22U6D3V3MX-1-GP  [C603H40]  90.16 185.87 180 top
PC4840  SC22U6D3V3MX-1-GP  [C603H40]  88.89 185.87 180 top
PC4841  SC22U6D3V3MX-1-GP  [C603H40]  105.07 186.18 270 bottom
PC4842  SC22U6D3V3MX-1-GP  [C603H40]  105.07 187.45 270 bottom
PC4901  SC22U6D3V3MX-1-GP  [C603H40]  101.74 181.76 270 top
PC4902  SC22U6D3V3MX-1-GP  [C603H40]  98.16 180.11 0 top
PC4903  SC4D7U6D3V2MX-GP-U  [C402-TO0D2H26]  105.9 161.49 180 top
PC4904  SC4D7U6D3V2MX-GP-U  [C402-TO0D2H26]  106.54 166.7 270 top
PC4905  SC1U16V2KX-GP  [C402H22]  109.87 172.23 0 bottom
PC4906  SC1U16V2KX-GP  [C402H22]  89.14 168.45 180 bottom
PC4907  SC1U16V2KX-GP  [C402H22]  99.05 177.11 180 top
PC4908  SC1U16V2KX-GP  [C402H22]  110.3 176.96 180 bottom
PC4909  SC1U16V2KX-GP  [C402H22]  104.76 177.36 180 top
PC4910  SC22U6D3V3MX-1-GP  [C603H40]  96.63 177.87 90 top
PC4912  SC1U16V2KX-GP  [C402H22]  111.06 176.96 180 bottom
PC4913  SC10U6D3V2MX-GP-U  [C402-TO0D2H28]  99.3 179.27 0 top
PC4914  SC10U6D3V2MX-GP-U  [C402-TO0D2H28]  104.51 173.93 0 top
PC4915  SC22U6D3V3MX-1-GP  [C603H40]  103.11 172.41 0 top
PC4916  SC1U16V2KX-GP  [C402H22]  110.63 172.23 0 bottom
PC4917  SC1U16V2KX-GP  [C402H22]  105.78 174.06 270 top
PC4918  SC1U16V2KX-GP  [C402H22]  99.3 171.29 180 top
PC4919  SC1U16V2KX-GP  [C402H22]  107.3 185.49 90 bottom
PC5001  SCD1U16V1KX-GP  [C0201H13]  104.38 182.54 0 bottom
PC5003  SCD1U16V1KX-GP  [C0201H13]  110.76 179.27 180 top
PC5004  SC1U16V2KX-GP  [C402H22]  91.17 162.63 270 top
PC5005  20KR2F-L-GP  [R402H16]  92.82 162.63 270 top
PC5101  SC1U16V2KX-GP  [C402H22]  103.49 158.69 270 bottom
PC5102  SC1U16V2KX-GP  [C402H22]  97.78 170.76 0 top
PC5103  SC1U16V2KX-GP  [C402H22]  104.89 153.87 0 bottom
PC5104  SC1U16V2KX-GP  [C402H22]  106.29 157.04 270 bottom
PD4601  SD103AWS-2-GP  [SOD323AKH38]  96.25 102.56 180 top
PD4604  UDZV-5D6B-GP  [SOD323-2513AKH36]  106.18 83.33 270 top
PD4605  SD103AWS-2-GP  [SOD323AKH38]  92.19 90.62 270 top
PD4606  SD103AWS-2-GP  [SOD323AKH38]  97.52 132.15 90 top
PD4607  SMD34JGP-GP-U  [SOD123AK-3719-UH40]  91.25 83.18 90 top
PD4801  CDZGT2RA6D2B-GP  [D1006-0304AKH16]  107.1 179.93 0 bottom
PD5101  BAT54C-7-F-3-GP  [SOT23-2D4-312H48]  105.9 159.33 270 bottom
PG4601  GAP-CLOSE-PWR-3-GP  [GAP-CLOSE-PWR-3]  89.65 90.75 0 top
